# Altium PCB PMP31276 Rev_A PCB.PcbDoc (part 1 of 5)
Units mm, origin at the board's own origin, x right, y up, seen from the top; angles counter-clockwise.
Board outline 228.6 x 203.2 mm, 4 copper layers (Top Layer, Layer 1, Layer 2, Bottom Layer), stack 1.998 mm thick; 375 components, 187 nets, 994 pads, 546 vias.
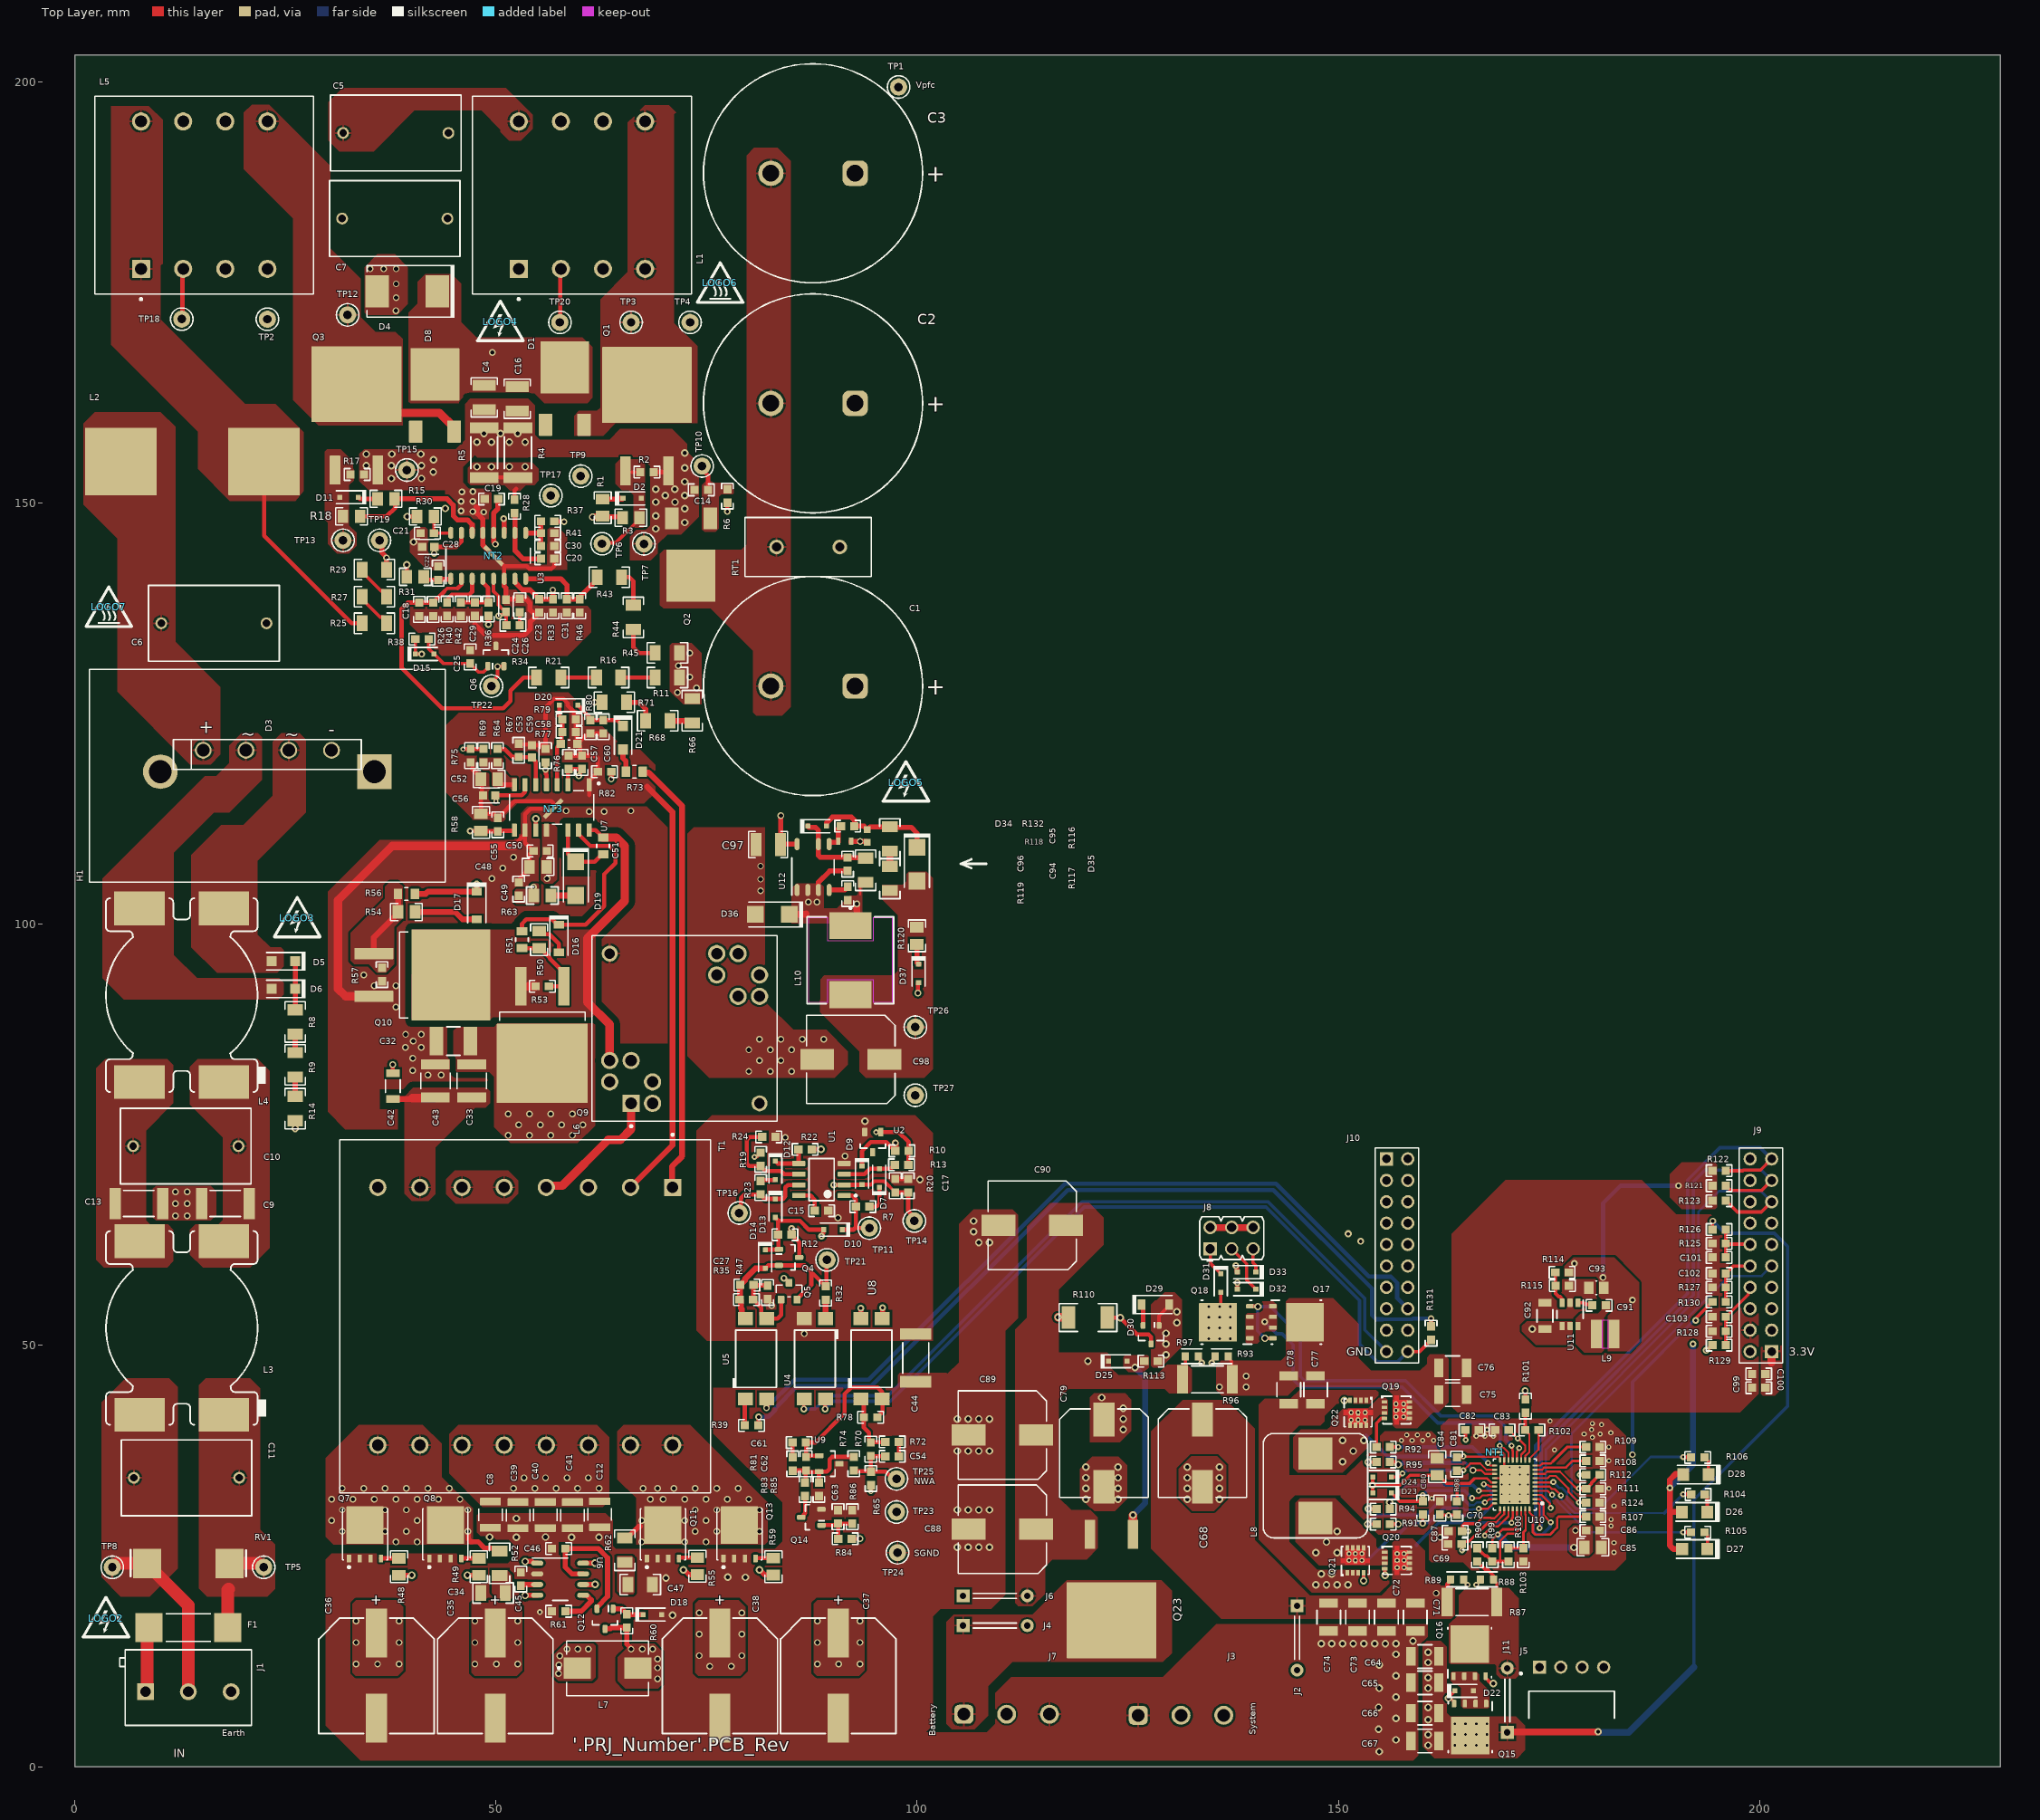
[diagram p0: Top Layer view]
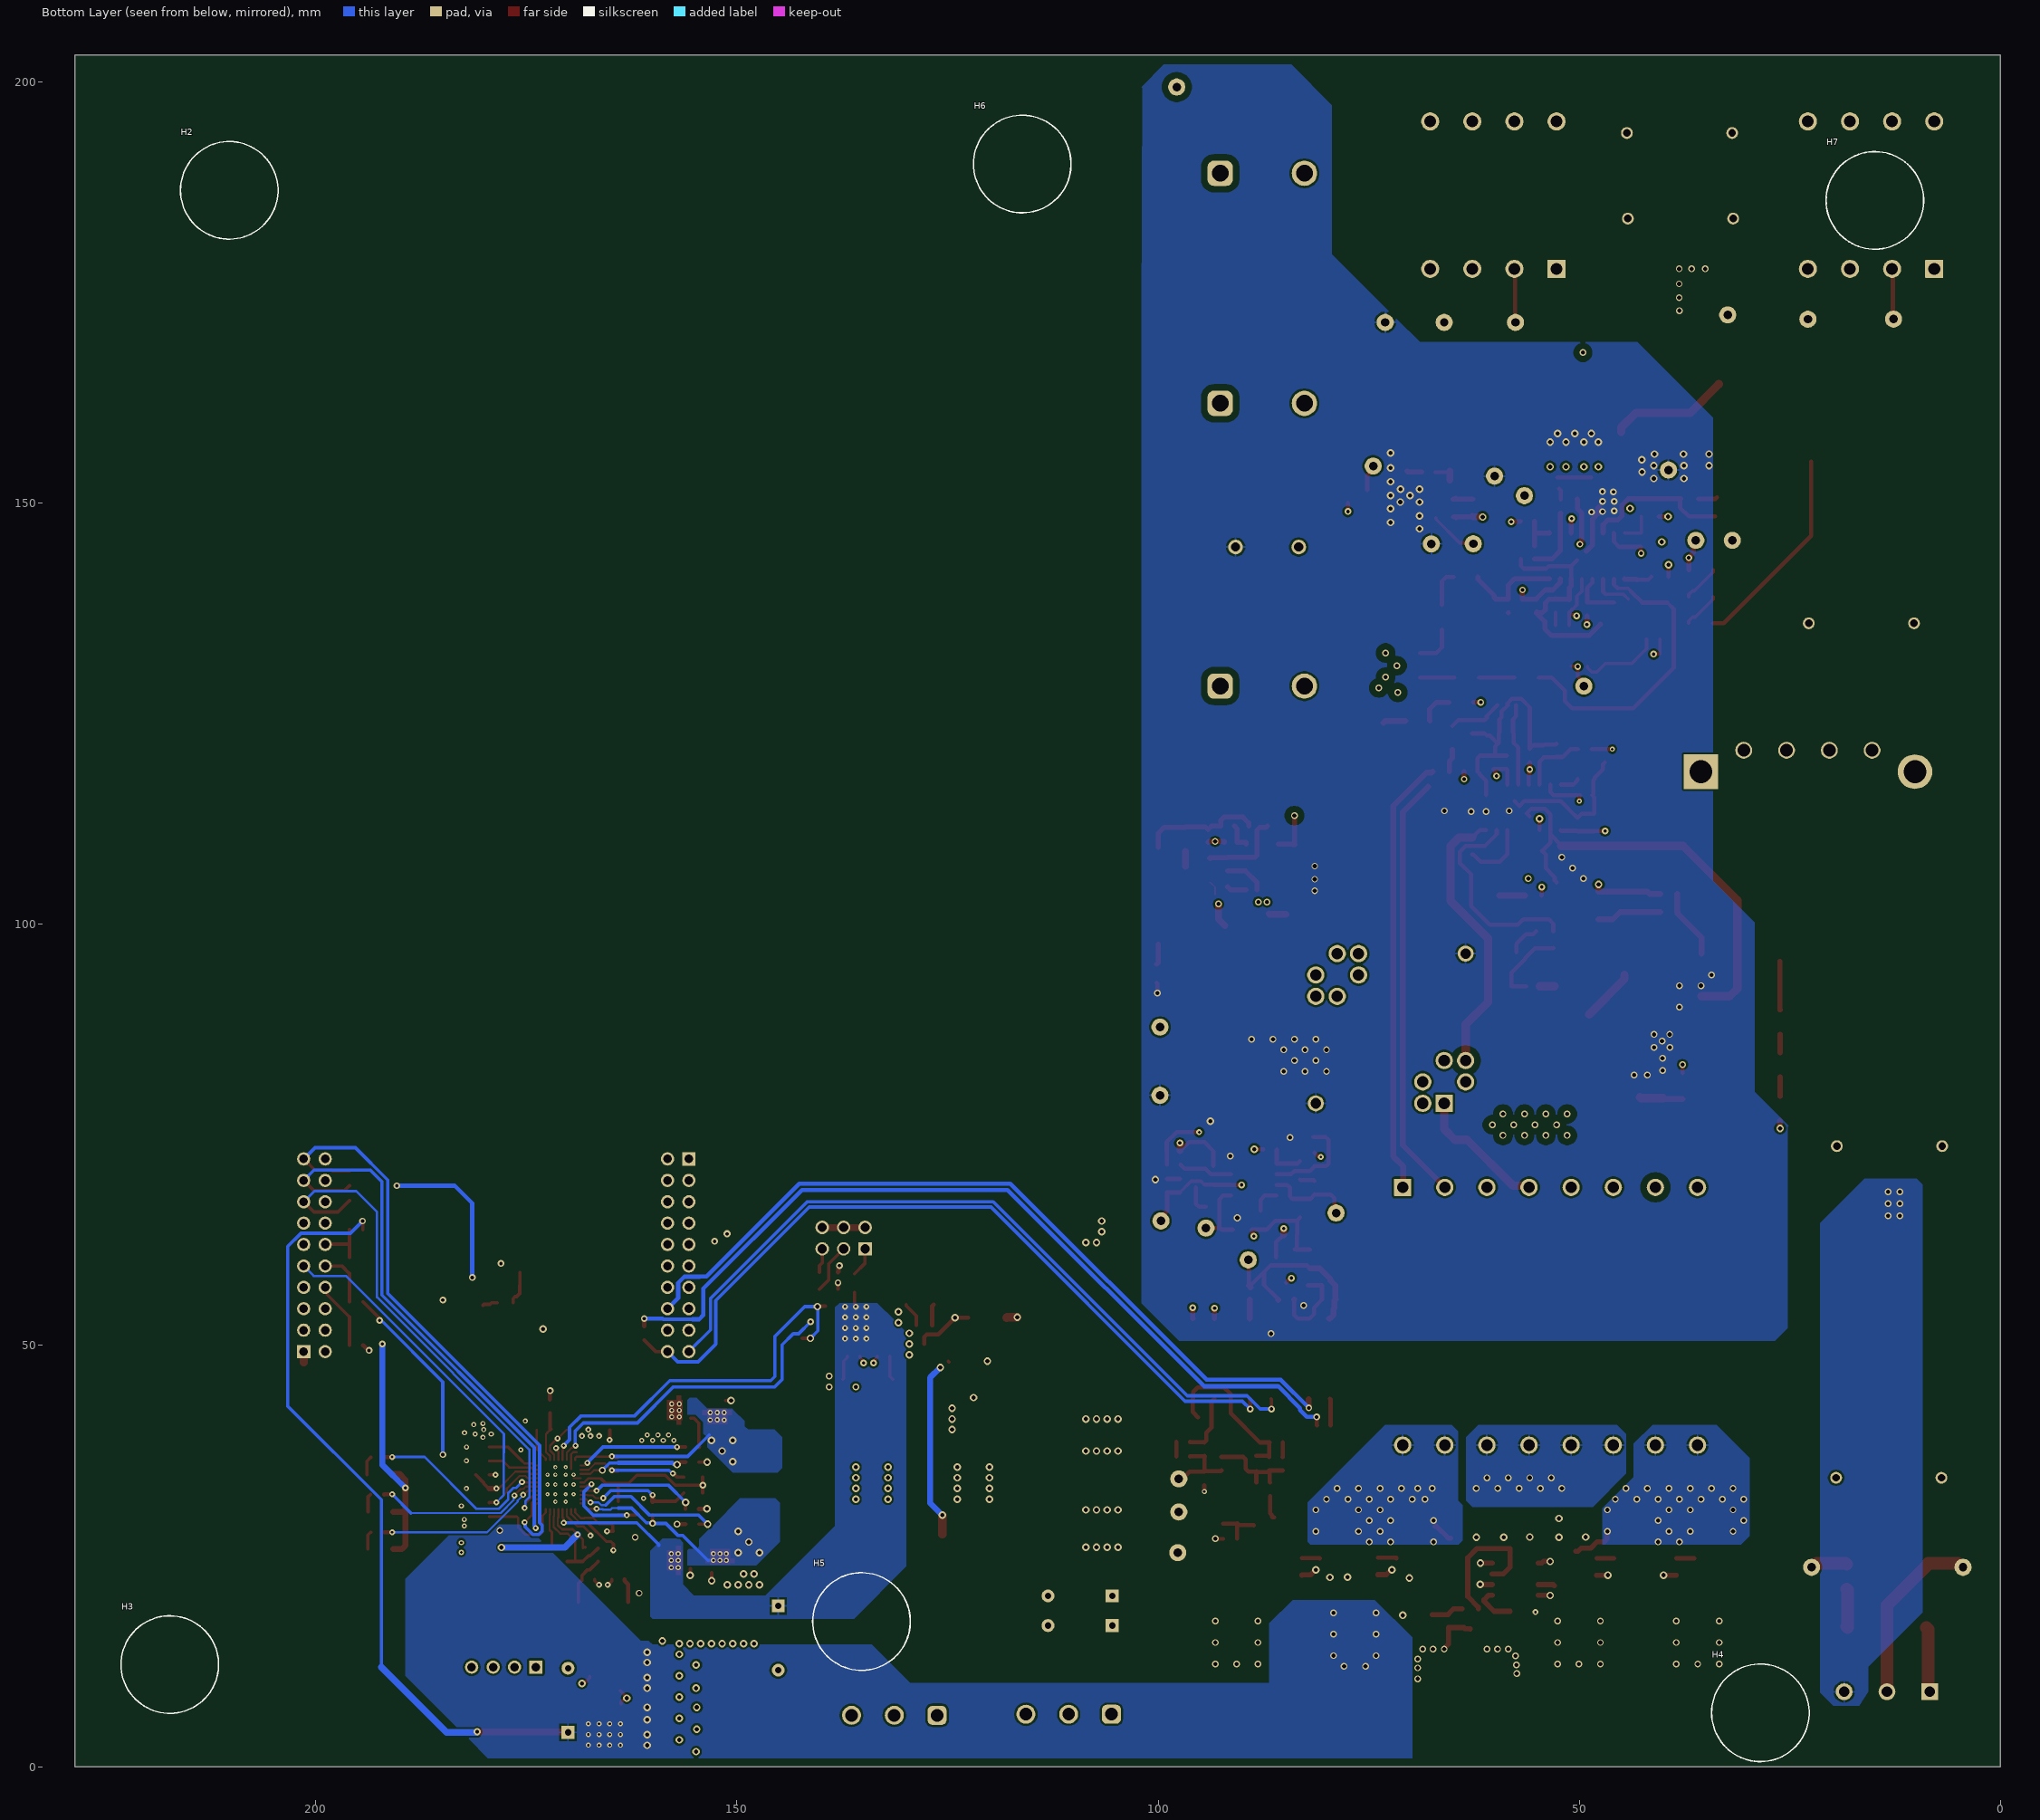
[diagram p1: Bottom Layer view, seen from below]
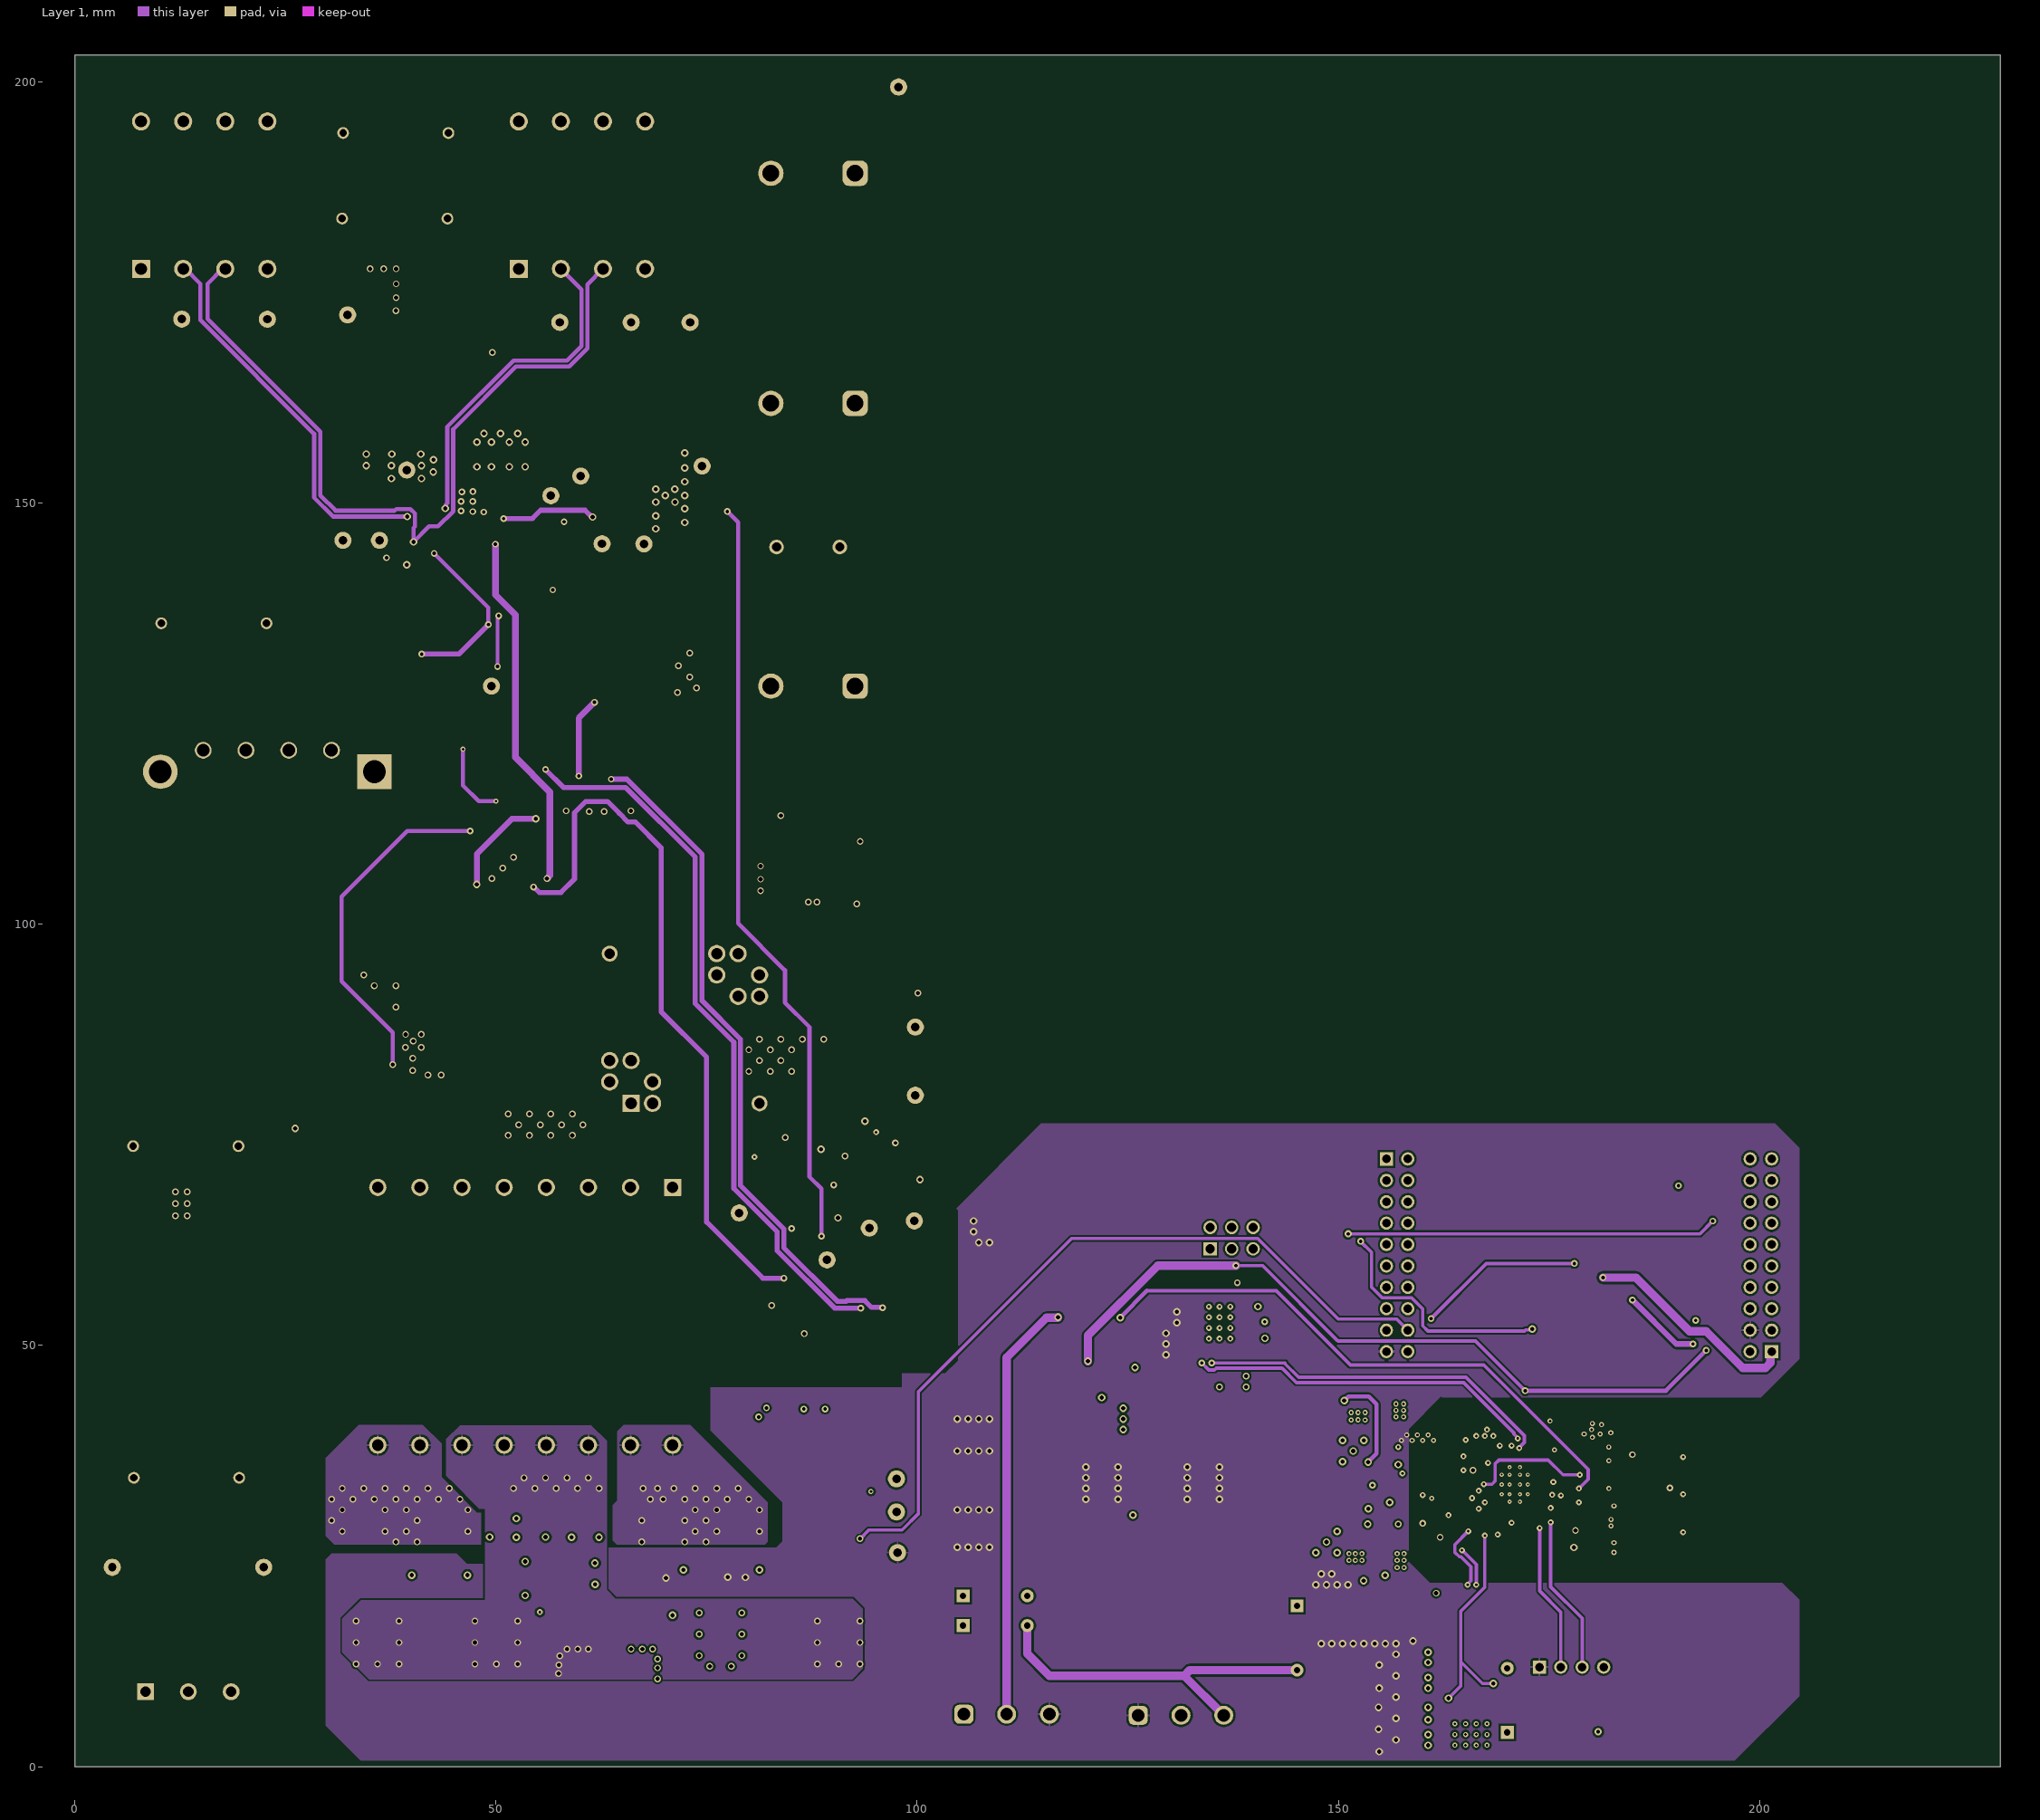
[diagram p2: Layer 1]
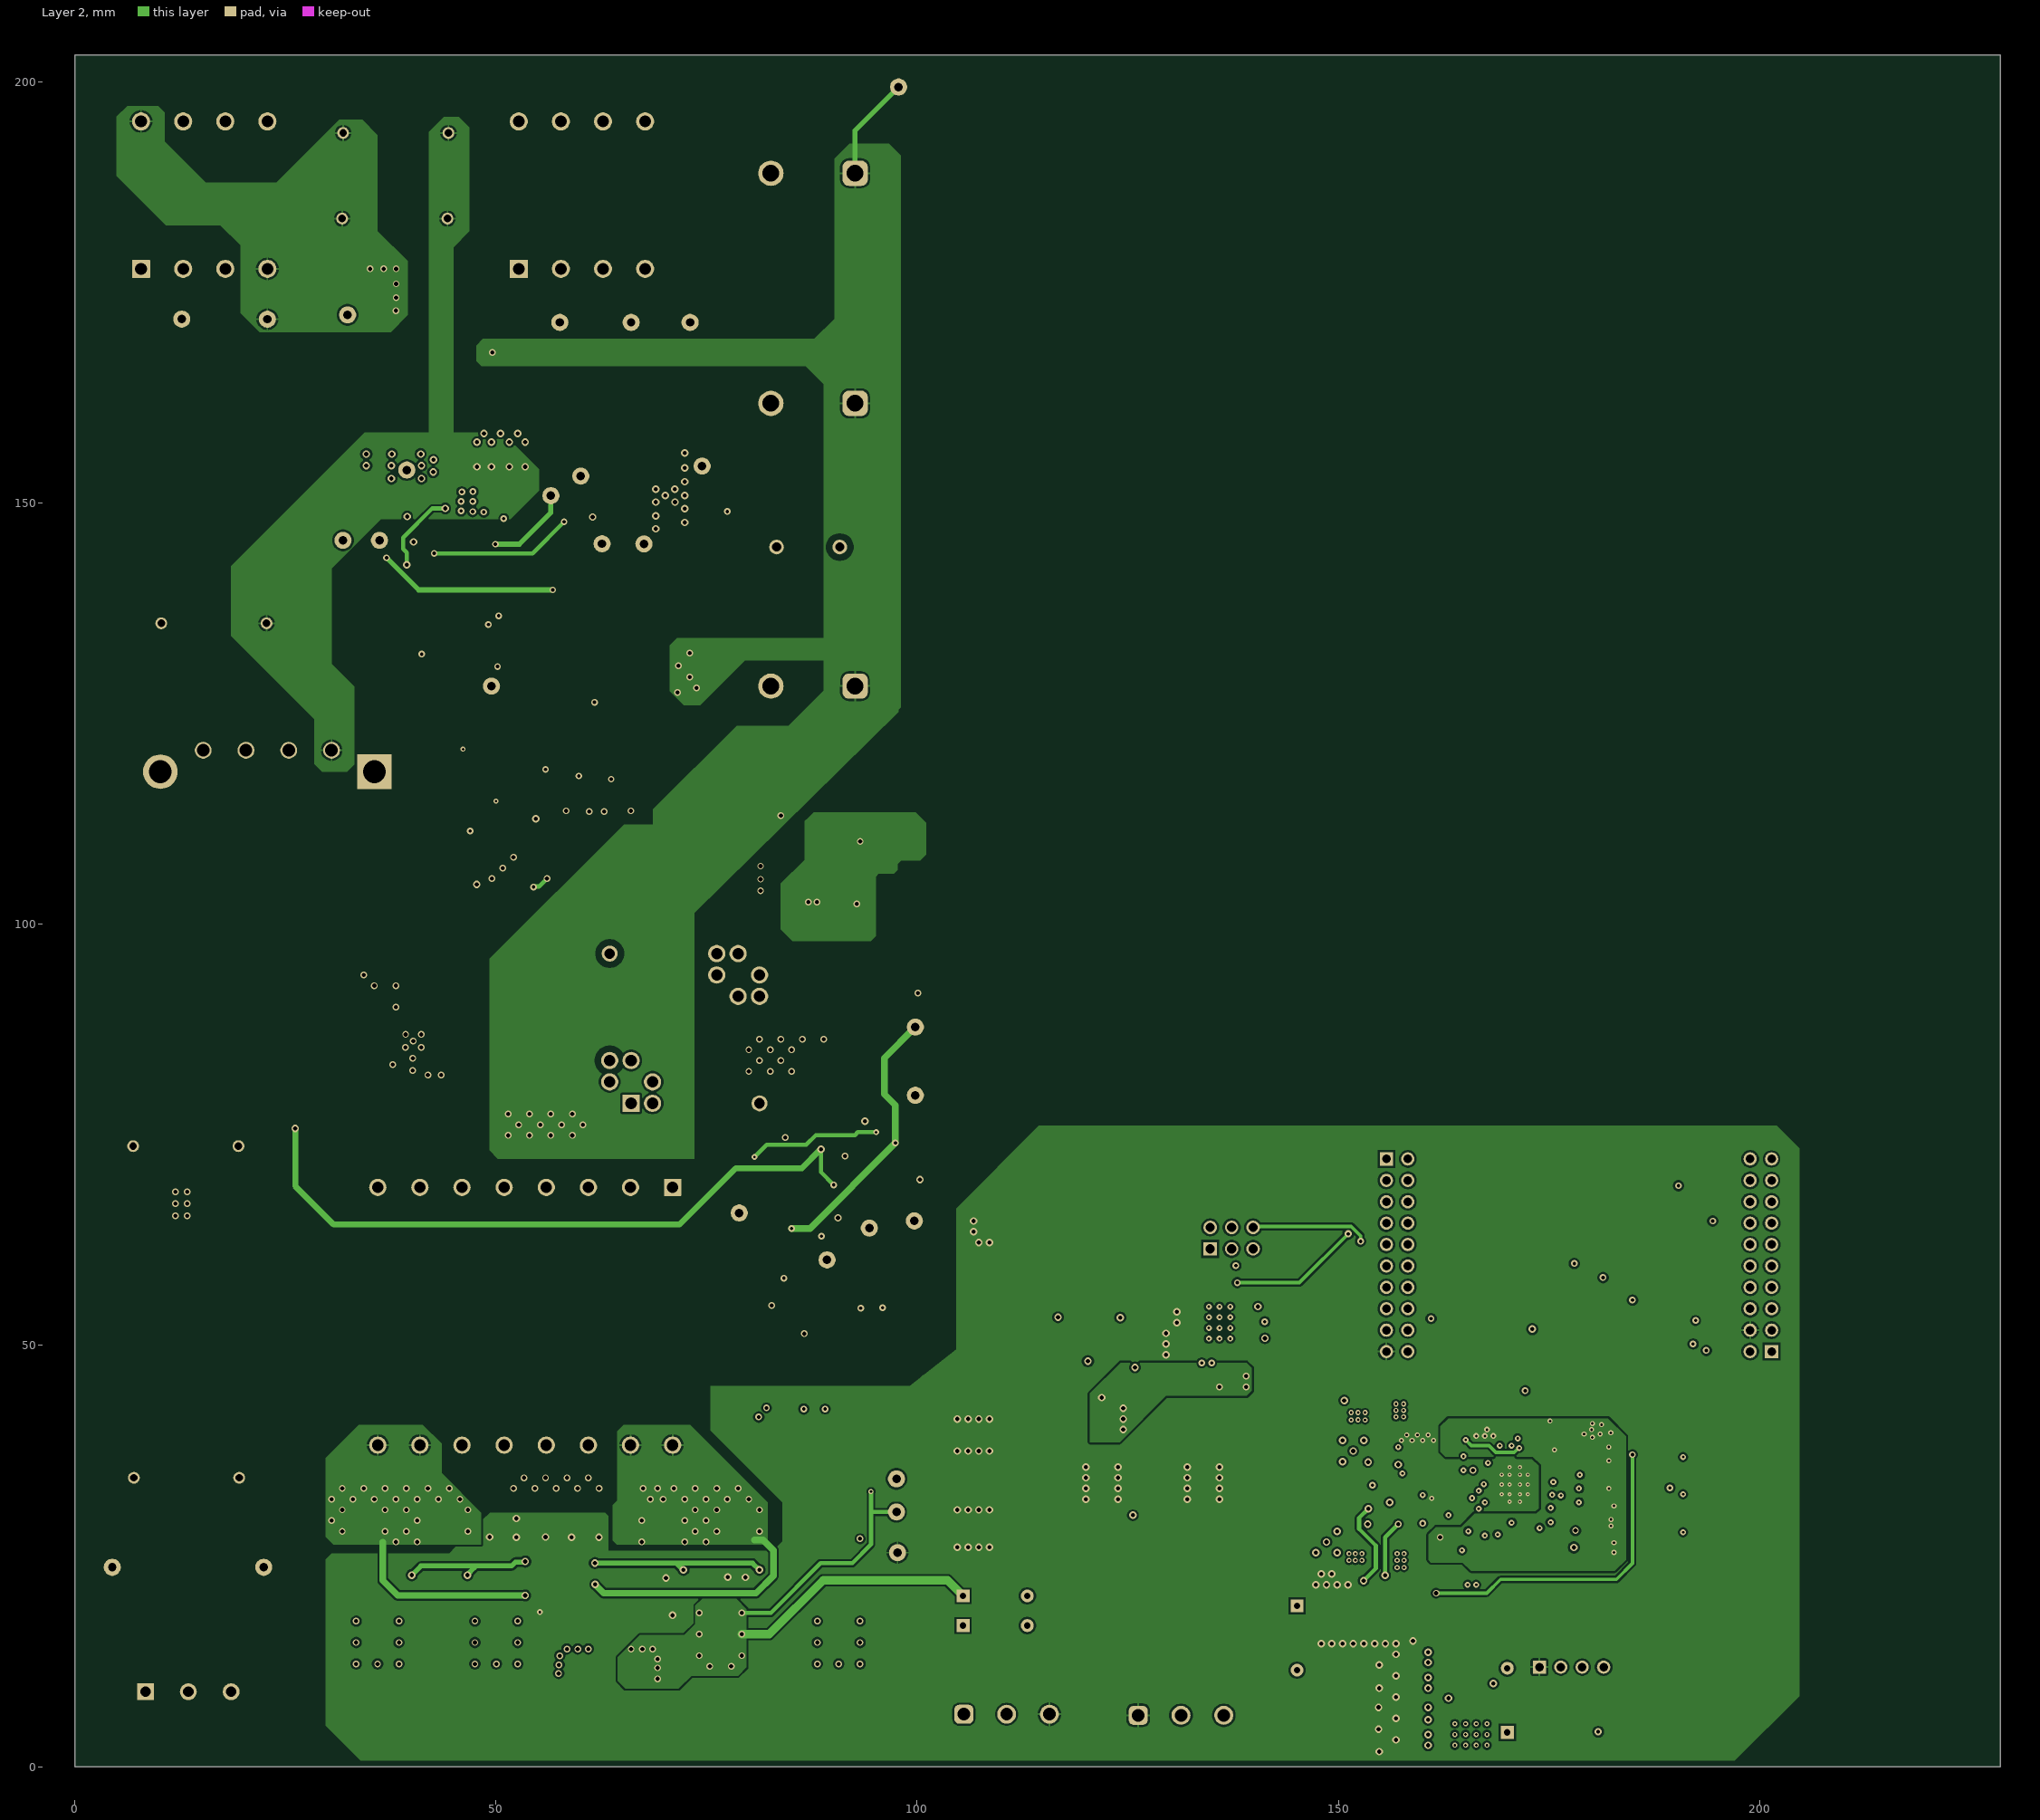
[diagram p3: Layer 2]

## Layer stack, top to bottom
Top Solder: solder mask 0.0102, Solder Resist, Dk 3.5
Top Layer: signal copper 0.07
Dielectric 1: prepreg 0.0711, PP-006, Dk 4.1
Layer 1: signal copper 0.035
Dielectric 3: prepreg 0.0711, PP-006, Dk 4.1
Dielectric1: core 1.5037, FR-4 High Tg, Dk 4.8
Dielectric 4: prepreg 0.0711, PP-006, Dk 4.1
Layer 2: signal copper 0.035
Dielectric 2: prepreg 0.0711, PP-006, Dk 4.1
Bottom Layer: signal copper 0.07
Bottom Solder: solder mask 0.0102, Solder Resist, Dk 3.5

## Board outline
0,0 228.6,0 228.6,203.2 0,203.2

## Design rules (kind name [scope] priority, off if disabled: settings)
AcuteAngle [All] p1: minimum=4.50000000000000E+0001 checktracksonly=FALSE
AssemblyTestPointUsage [All] p1: valid=2
BoardOutlineClearance BoardOutlineClearance_MountingHoles [OnCopper and InComponentClass('Mounting Holes')] p1: gap=1 ignorepadtopadclearanceinfootprint=FALSE
BoardOutlineClearance BoardOutlineClearance_Poly [OnCopper and IsPoly] p2: gap=0.635 ignorepadtopadclearanceinfootprint=FALSE
BoardOutlineClearance [OnCopper and Not InComponentClass('Logo') and not InComponentClass('FiducialMark') and not InRegion(1000,500,4000,800) and not InPoly] p3: gap=1.016 ignorepadtopadclearanceinfootprint=FALSE
Clearance "Clearance HV" [InNet('SW') vs InNet('PGND')] p1: gap=0.75 ignorepadtopadclearanceinfootprint=TRUE
Clearance "Clearance HV_1" [InNet('SW') vs InNet('Vpfc')] p2: gap=0.75 ignorepadtopadclearanceinfootprint=TRUE
Clearance "Clearance Q9-gate" [InNet('NetQ9_1') vs InNet('PGND')] p3: gap=0.75 ignorepadtopadclearanceinfootprint=TRUE
Clearance "Clearance HDRV-G" [InNet('HDRV-G') vs InNet('PGND')] p4: gap=0.75 ignorepadtopadclearanceinfootprint=TRUE
Clearance "Clearance C51-2" [InNet('NetC51_2') vs InNet('PGND')] p5: gap=0.75 ignorepadtopadclearanceinfootprint=TRUE
Clearance "Clearance Vpfc" [InNet('Vpfc') vs InNet('PGND')] p6: gap=0.75 ignorepadtopadclearanceinfootprint=TRUE
Clearance "Clearance C33-1" [InNet('NetC33_1') vs InNet('PGND')] p7: gap=0.75 ignorepadtopadclearanceinfootprint=TRUE
Clearance Clearance_U10 [InComponent('U10')] p8: gap=0.25 ignorepadtopadclearanceinfootprint=TRUE
Clearance "Schematic Clearance Constraint_54" [InNet('3V3')] p9: gap=0.254 ignorepadtopadclearanceinfootprint=FALSE
Clearance "Schematic Clearance Constraint_53" [InNet('AGND')] p10: gap=0.254 ignorepadtopadclearanceinfootprint=FALSE
Clearance "Schematic Clearance Constraint_52" [InNet('BAT_SRC')] p11: gap=0.254 ignorepadtopadclearanceinfootprint=FALSE
Clearance "Schematic Clearance Constraint_51" [InNet('BQ_CE')] p12: gap=0.254 ignorepadtopadclearanceinfootprint=FALSE
Clearance "Schematic Clearance Constraint_50" [InNet('NetD22_2')] p13: gap=0.254 ignorepadtopadclearanceinfootprint=FALSE
Clearance "Schematic Clearance Constraint_49" [InNet('BAT')] p14: gap=0.254 ignorepadtopadclearanceinfootprint=FALSE
Clearance "Schematic Clearance Constraint_48" [InNet('NetJ11_2')] p15: gap=0.254 ignorepadtopadclearanceinfootprint=FALSE
Clearance "Schematic Clearance Constraint_47" [InNet('NetR114_1')] p16: gap=0.254 ignorepadtopadclearanceinfootprint=FALSE
Clearance "Schematic Clearance Constraint_46" [InNet('NetC91_2')] p17: gap=0.254 ignorepadtopadclearanceinfootprint=FALSE
Clearance "Schematic Clearance Constraint_45" [InNet('NetC75_1')] p18: gap=0.254 ignorepadtopadclearanceinfootprint=FALSE
Clearance "Schematic Clearance Constraint_44" [InNet('NetC92_2')] p19: gap=0.254 ignorepadtopadclearanceinfootprint=FALSE
Clearance "Schematic Clearance Constraint_43" [InNet('24V/27.6V')] p20: gap=0.229 ignorepadtopadclearanceinfootprint=FALSE
Clearance "Schematic Clearance Constraint_42" [InNet('AC_DC_on')] p21: gap=0.229 ignorepadtopadclearanceinfootprint=FALSE
Clearance "Schematic Clearance Constraint_41" [InNet('NetR92_2')] p22: gap=0.229 ignorepadtopadclearanceinfootprint=FALSE
Clearance "Schematic Clearance Constraint_40" [InNet('NetR100_1')] p23: gap=0.229 ignorepadtopadclearanceinfootprint=FALSE
Clearance "Schematic Clearance Constraint_39" [InNet('NetC102_1')] p24: gap=0.229 ignorepadtopadclearanceinfootprint=FALSE
Clearance "Schematic Clearance Constraint_38" [InNet('NetC70_2')] p25: gap=0.229 ignorepadtopadclearanceinfootprint=FALSE
Clearance "Schematic Clearance Constraint_37" [InNet('NetR102_2')] p26: gap=0.229 ignorepadtopadclearanceinfootprint=FALSE
Clearance "Schematic Clearance Constraint_36" [InNet('NetR105_2')] p27: gap=0.229 ignorepadtopadclearanceinfootprint=FALSE
Clearance "Schematic Clearance Constraint_35" [InNet('NetR94_2')] p28: gap=0.229 ignorepadtopadclearanceinfootprint=FALSE
Clearance "Schematic Clearance Constraint_34" [InNet('BQ_INT')] p29: gap=0.229 ignorepadtopadclearanceinfootprint=FALSE
Clearance "Schematic Clearance Constraint_33" [InNet('DRV_SUP')] p30: gap=0.229 ignorepadtopadclearanceinfootprint=FALSE
Clearance "Schematic Clearance Constraint_32" [InNet('NetQ22_4')] p31: gap=0.229 ignorepadtopadclearanceinfootprint=FALSE
Clearance "Schematic Clearance Constraint_31" [InNet('NetD29_1')] p32: gap=0.229 ignorepadtopadclearanceinfootprint=FALSE
Clearance "Schematic Clearance Constraint_30" [InNet('NetR101_2')] p33: gap=0.229 ignorepadtopadclearanceinfootprint=FALSE
Clearance "Schematic Clearance Constraint_29" [InNet('BAT_DRV')] p34: gap=0.229 ignorepadtopadclearanceinfootprint=FALSE
Clearance "Schematic Clearance Constraint_28" [InNet('NetJ7_2')] p35: gap=0.229 ignorepadtopadclearanceinfootprint=FALSE
Clearance "Schematic Clearance Constraint_27" [InNet('NetC101_1')] p36: gap=0.229 ignorepadtopadclearanceinfootprint=FALSE
Clearance "Schematic Clearance Constraint_26" [InNet('SDA')] p37: gap=0.229 ignorepadtopadclearanceinfootprint=FALSE
Clearance "Schematic Clearance Constraint_25" [InNet('NetC81_1')] p38: gap=0.229 ignorepadtopadclearanceinfootprint=FALSE
Clearance "Schematic Clearance Constraint_24" [InNet('NetC83_1')] p39: gap=0.229 ignorepadtopadclearanceinfootprint=FALSE
Clearance "Schematic Clearance Constraint_23" [InNet('NetR95_2')] p40: gap=0.229 ignorepadtopadclearanceinfootprint=FALSE
Clearance "Schematic Clearance Constraint_22" [InNet('NetQ20_4')] p41: gap=0.229 ignorepadtopadclearanceinfootprint=FALSE
Clearance "Schematic Clearance Constraint_21" [InNet('SYSTEM')] p42: gap=0.229 ignorepadtopadclearanceinfootprint=FALSE
Clearance "Schematic Clearance Constraint_20" [InNet('NetJ4_1')] p43: gap=0.229 ignorepadtopadclearanceinfootprint=FALSE
Clearance "Schematic Clearance Constraint_19" [InNet('NetD22_1')] p44: gap=0.229 ignorepadtopadclearanceinfootprint=FALSE
Clearance "Schematic Clearance Constraint_18" [InNet('NetD25_2')] p45: gap=0.229 ignorepadtopadclearanceinfootprint=FALSE
Clearance "Schematic Clearance Constraint_17" [InNet('NetQ21_4')] p46: gap=0.229 ignorepadtopadclearanceinfootprint=FALSE
Clearance "Schematic Clearance Constraint_16" [InNet('NetR107_2')] p47: gap=0.229 ignorepadtopadclearanceinfootprint=FALSE
Clearance "Schematic Clearance Constraint_15" [InNet('NetC80_2')] p48: gap=0.229 ignorepadtopadclearanceinfootprint=FALSE
Clearance "Schematic Clearance Constraint_14" [InNet('NetR109_2')] p49: gap=0.229 ignorepadtopadclearanceinfootprint=FALSE
Clearance "Schematic Clearance Constraint_13" [InNet('NetR91_1')] p50: gap=0.229 ignorepadtopadclearanceinfootprint=FALSE
Clearance "Schematic Clearance Constraint_12" [InNet('NetC82_2')] p51: gap=0.229 ignorepadtopadclearanceinfootprint=FALSE
Clearance "Schematic Clearance Constraint_11" [InNet('NetC80_1')] p52: gap=0.229 ignorepadtopadclearanceinfootprint=FALSE
Clearance "Schematic Clearance Constraint_10" [InNet('NetR104_2')] p53: gap=0.229 ignorepadtopadclearanceinfootprint=FALSE
Clearance "Schematic Clearance Constraint_9" [InNet('NetR90_1')] p54: gap=0.229 ignorepadtopadclearanceinfootprint=FALSE
Clearance "Schematic Clearance Constraint_8" [InNet('NetC81_2')] p55: gap=0.229 ignorepadtopadclearanceinfootprint=FALSE
Clearance "Schematic Clearance Constraint_7" [InNet('NetQ19_4')] p56: gap=0.229 ignorepadtopadclearanceinfootprint=FALSE
Clearance "Schematic Clearance Constraint_6" [InNet('NetC103_1')] p57: gap=0.229 ignorepadtopadclearanceinfootprint=FALSE
Clearance "Schematic Clearance Constraint_5" [InNet('NetR108_2')] p58: gap=0.229 ignorepadtopadclearanceinfootprint=FALSE
Clearance "Schematic Clearance Constraint_4" [InNet('REG_N')] p59: gap=0.229 ignorepadtopadclearanceinfootprint=FALSE
Clearance "Schematic Clearance Constraint_3" [InNet('VAC_OK_SEC')] p60: gap=0.229 ignorepadtopadclearanceinfootprint=FALSE
Clearance "Schematic Clearance Constraint_2" [InNet('SCL')] p61: gap=0.229 ignorepadtopadclearanceinfootprint=FALSE
Clearance "Schematic Clearance Constraint_1" [InNet('NetC69_1')] p62: gap=0.229 ignorepadtopadclearanceinfootprint=FALSE
Clearance "Schematic Clearance Constraint" [InNet('NetR106_2')] p63: gap=0.229 ignorepadtopadclearanceinfootprint=FALSE
Clearance Clearance_Keepouts [((IsTrack Or IsArc) And Not InPoly) And IsFree and IsKeepOut vs ((IsTrack Or IsArc) And Not InPoly) And IsFree and IsKeepOut] p64: gap=0 ignorepadtopadclearanceinfootprint=FALSE
Clearance Clearance_Poly [InPolygon] p65: gap=0.254 ignorepadtopadclearanceinfootprint=TRUE except(0.2: Arc-Arc Arc-Track Arc-SMDPad Track-Track Track-SMDPad)
Clearance Clearance_FiducialMark [IsKeepOut and InComponentClass('FiducialMark') vs IsPad and InComponentClass('FiducialMark')] p66: gap=0 ignorepadtopadclearanceinfootprint=FALSE
Clearance "Clearance between HV Net and others" [InNetClass('HV') vs InNet('PGND')] p67: gap=1 ignorepadtopadclearanceinfootprint=TRUE
ComponentClearance ComponentClearance_1 [InComponent('NT2') vs InComponent('U3')] p1: gap=0 collisioncheckmode=3 verticalgap=0 showdistances=FALSE
ComponentClearance ComponentClearance_2 [InComponent('NT3') vs InComponent('U7')] p2: gap=0 collisioncheckmode=3 verticalgap=0 showdistances=FALSE
ComponentClearance ComponentClearance_MountingHoles_FiducialMarks [InComponentClass('Mounting Holes') vs InComponentClass('FiducialMark')] p3: gap=1.27 collisioncheckmode=3 verticalgap=0.254 showdistances=FALSE
ComponentClearance ComponentClearance_Shunt [InComponentClass('Header') vs InComponentClass('Shunt')] p4: gap=0 collisioncheckmode=3 verticalgap=0 showdistances=FALSE
ComponentClearance ComponentClearance_Logo [InComponentClass('Logo')] p5: gap=0.762 collisioncheckmode=3 verticalgap=0.254 showdistances=FALSE
ComponentClearance ComponentClearance_ScrewToNut [(HasFootprint('NY PMS 440 0025 PH')) vs (HasFootprint('Keystone_1902C'))] p6: gap=0.127 collisioncheckmode=3 verticalgap=0.254 showdistances=FALSE
ComponentClearance ComponentClearance_MountingHoles [InComponentClass('Mounting Holes')] p7: gap=2.54 collisioncheckmode=3 verticalgap=2540 showdistances=FALSE
ComponentClearance ComponentClearance_SmallPassives [HasFootprint('0201*') or HasFootprint('0402*') or HasFootprint('0508') or HasFootprint('0603*') or HasFootprint('0612') or HasFootprint('0805*') or HasFootprint('0815*') or HasFootprint('0830*') or HasFootprint('1206*') or HasFootprint('1210*') or HasFootprint('1808*') or HasFootprint('1812*') or HasFootprint('1825*') or HasFootprint('2010*') or HasFootprint('2220*') or HasFootprint('2225*') or HasFootprint('2512*') or HasFootprint('2728*') or HasFootprint('3518*') vs HasFootprint('0201*') or HasFootprint('0402*') or HasFootprint('0508') or HasFootprint('0603*') or HasFootprint('0612') or HasFootprint('0805*') or HasFootprint('0815*') or HasFootprint('0830*') or HasFootprint('1206*') or HasFootprint('1210*') or HasFootprint('1808*') or HasFootprint('1812*') or HasFootprint('1825*') or HasFootprint('2010*') or HasFootprint('2220*') or HasFootprint('2225*') or HasFootprint('2512*') or HasFootprint('2728*') or HasFootprint('3518*')] p8: gap=0.254 collisioncheckmode=3 verticalgap=0.254 showdistances=FALSE
ComponentClearance ComponentClearance_THtoSMT [IsThruComponent vs IsSMTComponent] p9: gap=0.762 collisioncheckmode=3 verticalgap=0.762 showdistances=FALSE
ComponentClearance ComponentClearance_THtoTH [IsThruComponent vs IsThruComponent] p10: gap=0.508 collisioncheckmode=3 verticalgap=0.762 showdistances=FALSE
ComponentClearance [All] p11: gap=0.508 collisioncheckmode=3 verticalgap=0.254 showdistances=FALSE
DiffPairsRouting [All] p1: maxlimit=2.54 minlimit=0.254 mostfreqgap=0.254 toplayer_minwidth=0.381 toplayer_maxwidth=0.381 toplayer_prefwidth=0.381 midlayer1_minwidth=0.381 midlayer1_maxwidth=0.381 midlayer1_prefwidth=0.381 midlayer2_minwidth=0.381 midlayer2_maxwidth=0.381 midlayer2_prefwidth=0.381 bottomlayer_minwidth=0.381 bottomlayer_maxwidth=0.381 bottomlayer_prefwidth=0.381 maxuncoupledlength=25.4
FabricationTestPointUsage TestPointUsage [All] p1: valid=2 allowmultiple=FALSE
FabricationTestpoint Testpoint [All] p1: side=3 testpointundercomponent=TRUE minsize=1.016 maxsize=2.54 preferedsize=1.524 minholesize=0 maxholesize=1.016 preferedholesize=0.813 testpointgrid=0.025 allowsidetop=TRUE allowsidebottom=TRUE usegrid=TRUE gridtolerance=0
FanoutControl Fanout_LCC [IsLCC] p1: bgadir=Out bgaviamode=Centered fanoutstyle=Auto fanoutdirection=Alternating viagrid=0.025 // Fanout_LCC (Default Rule)
FanoutControl Fanout_BGA [IsBGA] p2: bgadir=Out bgaviamode=Centered fanoutstyle=Auto fanoutdirection=Alternating viagrid=0.025 // Fanout_BGA (Default Rule)
FanoutControl Fanout_Default [All] p4: bgadir=Out bgaviamode=Centered fanoutstyle=Auto fanoutdirection=Alternating viagrid=0.025 // Fanout_Default (Default Rule)
FanoutControl Fanout_Small [(CompPinCount < 5)] p5: bgadir=Out bgaviamode=Centered fanoutstyle=Auto fanoutdirection=OutThenIn viagrid=0.025 // Fanout_Small (Default Rule)
HoleSize [All] p1: absolutevalues=TRUE maxlimit=6.375 minlimit=0.2 maxpercent=80.000 minpercent=20.000
MinimumAnnularRing MinimumAnnularRing_ThermalPadVias [IsVia and InAnyComponent] p1: minimumring=0.15
MinimumAnnularRing [All] p2: minimumring=0.15
MinimumSolderMaskSliver MinimumSolderMaskSliver_Logo [InComponentClass('Logo') vs InComponentClass('Logo')] p1: minsoldermaskwidth=0.018
MinimumSolderMaskSliver [All] p2: minsoldermaskwidth=0.1
PlaneConnect [All] p1: planeconnectstyle=Relief reliefexpansion=0.254 reliefentries=4 reliefconductorwidth=0.254 reliefairgap=0.254
PolygonConnect PolygonConnect_1 [HasPad('U4-3')] p1: thpad.connectstyle=Relief thpad.reliefconductorwidth=0.254 thpad.reliefentries=4 thpad.polygonreliefangle="90 Angle" thpad.airgapwidth=0.254 smdpad.connectstyle=NoConnect smdpad.reliefconductorwidth=0.254 smdpad.reliefentries=4 smdpad.polygonreliefangle="90 Angle" smdpad.airgapwidth=0.254 via.connectstyle=Direct via.reliefconductorwidth=0.254 via.reliefentries=4 via.polygonreliefangle="90 Angle" via.airgapwidth=0.254
PolygonConnect [All] p2: thpad.connectstyle=Relief thpad.reliefconductorwidth=0.254 thpad.reliefentries=4 thpad.polygonreliefangle="90 Angle" thpad.airgapwidth=0.254 smdpad.connectstyle=Direct smdpad.reliefconductorwidth=0.254 smdpad.reliefentries=4 smdpad.polygonreliefangle="90 Angle" smdpad.airgapwidth=0.254 via.connectstyle=Direct via.reliefconductorwidth=0.254 via.reliefentries=4 via.polygonreliefangle="90 Angle" via.airgapwidth=0.254
RoutingVias ThermalPadVias [IsVia and InAnyComponent] p1: holewidth=0.2 width=0.5 viastyle="Through Hole" minholewidth=0.2 minwidth=0.5 maxholewidth=0.33 maxwidth=0.6
RoutingVias [All] p2: holewidth=0.406 width=0.864 viastyle="Through Hole" minholewidth=0.2 minwidth=0.5 maxholewidth=1.016 maxwidth=1.651
SilkToBoardRegionClearance [Not ((IsComment or IsDesignator) And (Hide <> 'False')) and not InRegion(1000,500,4000,800)] p1:
SilkToSilkClearance SilkToSilkClearance_Pb-FreeLogo [(HasFootprint('Pb-Free_Overlay_Medium') OR HasFootprint('Pb-Free_Overlay_Small')) vs (HasFootprint('Pb-Free_Overlay_Medium') OR HasFootprint('Pb-Free_Overlay_Small'))] p1: silktosilkclearance=0
SilkToSilkClearance [All] p2: silktosilkclearance=0.1
SilkToSolderMaskClearance SilkToComponentPadClearance [(IsPad or IsFill or IsRegion) and InAnycomponent] p1: minsilkscreentomaskgap=0.127 clearancetoexposedcopper=TRUE
SilkToSolderMaskClearance "Silk to Solder Mask Opening" [All] p2: minsilkscreentomaskgap=0.1 clearancetoexposedcopper=FALSE
SolderMaskExpansion [All] p1: expansion=0.05 istentingtop=FALSE
UnRoutedNet [All] p1: checkbadconnections=TRUE
Width [All] p1: maxlimit=2.54 minlimit=0.152 preferedwidth=0.254 checkconnectedcopper=TRUE
14 further rules are at their usual default settings.

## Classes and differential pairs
net class HV: net_D1_3 NetC6_2 NetD5_1 NetD8_3 VAC Vpfc
component class "PMP31276 Rev_A PFC Schematic": C1 C2 C3 C4 C5 C6 C7 C9 C10 C11 C13 C14 C15 C16 C17 C18 C19 C20 C21 C22 C23 C24 C25 C26 C27 C28 C29 C30 C31 D1 D2 D3 D4 D5 D6 D7 D8 D9 D10 D11 D12 D13 D14 D15 F1 H1 J1 L1 L2 L3 L4 L5 NT2 Q1 Q2 Q3 Q4 Q5 Q6 R1 R2 R3 R4 R5 R6 R7 R8 R9 R10 R11 R12 R13 R14 R15 R16 R17 R18 R19 R20 R21 R22 R23 R24 R25 R26 R27 R28 R29 R30 R31 R32 R33 R34 R35 R36 R37 R38 R39 R40 R41 R42 R43 R44 R45 R46 R47 RT1 RV1 TP1 TP2 TP3 TP4 TP5 TP6 TP7 TP8 TP9 TP10 TP11 TP12 TP13 TP14 TP15 TP16 TP17 TP18 TP19 TP20 TP21 TP22 U1 U2 U3 U4 U5
component class "PMP31276 Rev_A LLC Schematic": C8 C12 C32 C33 C34 C35 C36 C37 C38 C39 C40 C41 C42 C43 C44 C45 C46 C47 C48 C49 C50 C51 C52 C53 C54 C55 C56 C57 C58 C59 C60 C61 C62 C63 D16 D17 D18 D19 D20 D21 L6 L7 NT3 Q7 Q8 Q9 Q10 Q11 Q12 Q13 Q14 R48 R49 R50 R51 R52 R53 R54 R55 R56 R57 R58 R59 R60 R61 R62 R63 R64 R65 R66 R67 R68 R69 R70 R71 R72 R73 R74 R75 R76 R77 R78 R79 R80 R81 R82 R83 R84 R85 R86 T1 TP23 TP24 TP25 U6 U7 U8 U9
component class "PMP31276 Rev_A LaunchPad and Aux-PSU Schematic": C91 C92 C93 C94 C95 C96 C97 C98 C99 C100 C101 C102 C103 D31 D32 D33 D34 D35 D36 D37 J8 J9 J10 L9 L10 R114 R115 R116 R117 R118 R119 R120 R121 R122 R123 R124 R125 R126 R127 R128 R129 R130 R131 R132 TP26 TP27 U11 U12
component class "PMP31276 Rev_A Hardware": H2 H3 H4 H5 H6 H7 H8 H9 H10 LOGO2 LOGO3 LOGO4 LOGO5 LOGO6 LOGO7
component class "PMP31276 Rev_A Charger Schematic": C64 C65 C66 C67 C68 C69 C70 C71 C72 C73 C74 C75 C76 C77 C78 C79 C80 C81 C82 C83 C84 C85 C86 C87 C88 C89 C90 D22 D23 D24 D25 D26 D27 D28 D29 D30 J2 J3 J4 J5 J6 J7 J11 L8 NT1 Q15 Q16 Q17 Q18 Q19 Q20 Q21 Q22 Q23 R87 R88 R89 R90 R91 R92 R93 R94 R95 R96 R97 R98 R99 R100 R101 R102 R103 R104 R105 R106 R107 R108 R109 R110 R111 R112 R113 U10
component class Header: J8

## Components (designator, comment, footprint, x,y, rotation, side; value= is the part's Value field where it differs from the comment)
C1 "861141484010" WCAP-AI3H_D25H30 87.63,128.27 r0 top value=120uF
C2 "861141484010" WCAP-AI3H_D25H30 87.63,161.838 r0 top value=120uF
C3 "861141484010" WCAP-AI3H_D25H30 87.63,189.15 r0 top value=120uF
C4 "885342208009" 1210 48.599,162.54 r270 top value=0.01uF
C5 "890334024003" WCAP-FTXX_L15W8.5H14 38.1,193.929 r180 top value=0.33uF
C6 "890334024003" WCAP-FTXX_L15W8.5H14 16.51,135.73 r180 top value=0.33uF
C7 "890334024003" WCAP-FTXX_L15W8.5H14 37.988,183.769 r180 top value=0.33uF
C8 "885012209073" FP-885012209073_1210-MFG 49.336,29.905 r90 top value=10µF
C9 "8853522130151" WCAP-CSSA_2211_L5.7W2.8H2.5 17.871,66.847 r180 top value=2.2nF
C10 "890334024003" WCAP-FTXX_L15W8.5H14 13.174,73.66 r0 top value=0.33uF
C11 "890334024003" WCAP-FTXX_L15W8.5H14 13.266,34.29 r0 top value=0.33uF
C12 "885012209073" FP-885012209073_1210-MFG 62.316,29.955 r90 top value=10µF
C13 "8853522130151" WCAP-CSSA_2211_L5.7W2.8H2.5 7.598,66.847 r180 top value=2.2nF
C14 "GRM188R71E474KA12D" 0603 74.37,151.566 r180 top value=0.47uF
C15 "885012206095" 0603 88.646,66.002 r0 top value=0.1uF
C16 "885342208009" 1210 52.523,162.38 r270 top value=0.01uF
C17 "GRM188R6YA225KA12D" 0603 98.933,68.961 r90 top value=2.2uF
C18 "885012206083" 0603 40.894,137.381 r270 top value=1000pF
C19 "C1608X6S1H105K080AC" 0603 49.463,150.481 r180 top value=1uF
C20 "885012206083" 0603 56.134,143.383 r0 top value=1000pF
C21 "885012006054" 0603 41.846,146.431 r180 top value=33pF
C22 "885012006054" 0603 43.136,141.68 r90 top value=33pF
C23 "885012206083" 0603 55.118,137.795 r270 top value=1000pF
C24 "C0603C221J5GAC7867" FP-C0603C221J5GAC7867_0603-IPC_B 51.181,137.795 r270 top value=220pF
C25 "C1608X6S1H105K080AC" 0603 46.924,131.743 r90 top value=1uF
C26 "C1608X6S1H105K080AC" 0603 52.832,137.833 r90 top value=1uF
C27 "885012206095" 0603 79.785,57.173 r180 top value=0.1uF
C28 "885012206125" FP-885012206125_0603-IPC_B 41.968,144.79 r0 top value=220nF
C29 "885012206087" 0603 47.498,137.414 r270 top value=4700pF
C30 "885012206087" 0603 56.134,144.907 r0 top value=4700pF
C31 "885012206083" 0603 58.42,137.795 r270 top value=1000pF
C32 "885382211002" 1812_254 44.944,86.125 r180 top value=0.1uF
C33 "CKC18C103JDGACAUTO" FP-CKC18C103KWGACAUTO_1812-MFG 47.117,81.407 r90 top value=10nF
C34 "885012008070" 1206 49.665,20.613 r0 top value=330pF
C35 "865060562010" WCAP-ASLL_D12.5H14 49.911,10.795 r90 top value=680uF
C36 "865060562010" WCAP-ASLL_D12.5H14 35.814,10.795 r90 top value=680uF
C37 "865060562010" WCAP-ASLL_D12.5H14 90.638,10.795 r90 top value=680uF
C38 "865060562010" WCAP-ASLL_D12.5H14 76.581,10.795 r90 top value=680uF
C39 "885012209073" FP-885012209073_1210-MFG 52.608,29.854 r90 top value=10µF
C40 "885012209073" FP-885012209073_1210-MFG 55.851,29.873 r90 top value=10µF
C41 "885012209073" FP-885012209073_1210-MFG 59.079,29.854 r90 top value=10µF
C42 "885342208016" WCAP-CSMH_1206_L3.2W1.6H1.25 37.75,80.786 r270 top value=150pF
C43 "CKC18C103JDGACAUTO" FP-CKC18C103KWGACAUTO_1812-MFG 42.799,81.407 r270 top value=10nF
C44 "8853522130151" WCAP-CSSA_2211_L5.7W2.8H2.5 99.822,48.514 r270 top value=2.2nF
C45 "GRM188R6YA225KA12D" 0603 52.959,22.274 r270 top value=2.2uF
C46 "GRM188R6YA225KA12D" 0603 57.435,25.884 r180 top value=2.2uF
C47 "885012008070" 1206 67.13,21.625 r180 top value=330pF
C48 "C2012X7R1V475K125AC" 0805_HV 54.991,106.807 r180 top value=4.7uF
C49 "C1608X6S1H105K080AC" 0603 52.705,104.177 r90 top value=1uF
C50 "885012206095" 0603 55.245,108.712 r180 top value=0.1uF
C51 "Capacitor" 0805_HV1 62.715,109.292 r270 top value=1uF
C52 "C2012X7R1V475K125AC" 0805_HV 49.2,117.24 r180 top value=4.7uF
C53 "C0603C221J5GAC7867" FP-C0603C221J5GAC7867_0603-IPC_B 54.248,120.523 r270 top value=220pF
C54 "885012206087" 0603 97.028,36.83 r0 top value=4700pF
C55 "885012006057" 0603 50.209,111.818 r90 top value=100pF
C56 "C0603C221J5GAC7867" FP-C0603C221J5GAC7867_0603-IPC_B 49.196,115.302 r0 top value=220pF
C57 "C0603C222K5RAC" 0603 60.2,119.217 r90 top value=2200pF
C58 "C0603C222K5RAC" 0603 58.674,122.809 r0 top value=2200pF
C59 "885012006057" 0603 55.88,120.015 r90 top value=100pF
C60 "C1608X6S1H105K080AC" 0603 62.738,123.444 r270 top value=1uF
C61 "C1608X5R1H473K080AA" 0603 85.988,38.485 r0 top value=0.047uF
C62 "Capacitor" 0603 86.803,35.964 r270 top value=10pF
C63 "885012206087" 0603 90.6,29.666 r90 top value=4700pF
C64 "885012209073" 1210_280 160.274,13.081 r180 top value=10uF
C65 "885012209073" 1210_280 160.258,9.952 r180 top value=10uF
C66 "885012209073" 1210_280 160.274,6.35 r180 top value=10uF
C67 "885012209073" 1210_280 160.274,3.048 r180 top value=10uF
C68 "UCL1V151MCL6GS" SM_RADIAL_10BMM 133.858,37.211 r270 top value=150uF
C69 "GRM188R71E474KA12D" 0603 163.83,26.416 r180 top value=0.47uF
C70 "GRM188R71E474KA12D" 0603 163.874,27.944 r0 top value=0.47uF
C71 "885012209073" 1210_280 159.13,17.747 r270 top value=10uF
C72 "885012209073" 1210_280 155.701,17.747 r270 top value=10uF
C73 "885012209073" 1210_280 152.272,17.747 r270 top value=10uF
C74 "885012209073" 1210_280 148.843,17.747 r270 top value=10uF
C75 "885012209073" 1210_280 163.575,44.162 r0 top value=10uF
C76 "885012209073" 1210_280 163.575,47.338 r0 top value=10uF
C77 "885012209073" 1210_280 147.285,44.745 r270 top value=10uF
C78 "885012209073" 1210_280 144.11,44.745 r270 top value=10uF
C79 "UCL1V151MCL6GS" SM_RADIAL_10BMM 122.174,37.211 r270 top value=150uF
C80 "885012206095" 0603 160.019,30.701 r90 top value=0.1uF
C81 "885012206095" 0603 164.05,35.922 r270 top value=0.1uF
C82 "885012206095" 0603 165.861,39.972 r180 top value=0.1uF
C83 "885012206095" 0603 169.417,39.972 r180 top value=0.1uF
C84 "885012107018" 0805_HV 161.731,35.602 r90 top value=4.7uF
C85 "885012207103" 0805_HV 180.212,26.04 r0 top value=1uF
C86 "885012206095" 0603 180.212,28.034 r180 top value=0.1uF
C87 "885012206076" 0603 162.051,30.701 r270 top value=1uF
C88 "UCL1V151MCL6GS" SM_RADIAL_10BMM 110.109,28.194 r180 top value=150uF
C89 "UCL1V151MCL6GS" SM_RADIAL_10BMM 110.109,39.37 r180 top value=150uF
C90 "UCL1V151MCL6GS" SM_RADIAL_10BMM 113.656,64.258 r180 top value=150uF
C91 "885012206095" 0603 180.944,54.767 r0 top value=0.1uF
C92 "885012208094" FP-885012208094_1206-MFG 174.523,53.518 r270 top
C93 "885012107011" 0805_150 180.619,56.825 r180 top value=22uF
C94 "885012208069" 1206 93.886,106.398 r270 top value=10uF
C95 "885012006053" WCAP-CSGP_0603_L1.6W0.8H0.8_Reflow 94.082,110.487 r90 top value=22pF
C96 "885012206095" 0603 91.743,107.131 r90 top value=0.1uF
C97 "885342208009" 1210 82.303,109.458 r180 top value=0.01uF
C98 "UCL1V151MCL6GS" SM_RADIAL_10BMM 92.115,83.947 r180 top value=150uF
C99 "885012206026" 0603 199.898,44.99 r180 top value=1uF
C100 "885012206095" 0603 199.898,46.609 r0 top value=0.1uF
C101 "885012206083" 0603 195.199,60.452 r180 top value=1000pF
C102 "885012206083" 0603 195.199,58.547 r180 top value=1000pF
C103 "885012206083" 0603 195.199,53.397 r180 top value=1000pF
D1 "DTH8L06DNC" DPAK 58.166,162.687 r90 top
D2 "BAT54HT1G" SOD-323 66.167,150.55 r0 top
D3 "GBU10V08" GBU 22.86,120.658 r0 top value=800V
D4 "S3J-E3/57T" SMC 39.466,175.133 r180 top
D5 "SL1M" SOD-123F 24.765,95.606 r180 top
D6 "SL1M" SOD-123F 24.765,92.329 r180 top
D7 "BAS20HT1G" SOD-323 95.498,69.89 r90 top
D8 "DTH8L06DNC" DPAK 42.746,161.874 r90 top
D9 "BAS20HT1G" SOD-323 93.448,70.183 r270 top
D10 "BAS20HT1G" SOD-323 90.019,63.744 r180 top
D11 "BAT54HT1G" SOD-323 32.544,150.69 r180 top
D12 "BAS20HT1G" SOD-323 83.16,70.79 r270 top
D13 "BAS20HT1G" SOD-323 83.16,66.295 r270 top
D14 "BAS20HT1G" SOD-323 81.957,60.252 r270 top
D15 "BAT54HT1G" SOD-323 41.545,132.084 r0 top
D16 "RB160M-40TR" SOD-123 57.459,98.316 r270 top value=40V
D17 "RB160M-40TR" SOD-123 47.715,102.222 r270 top value=40V
D18 "MM3Z16VST1G" SOD-323 68.58,18.045 r0 top value=16V
D19 "DIODE" SMA 59.474,105.408 r270 top value=US1J-13-F
D20 "SZMM3Z18VST1G" SOD-323 58.608,126.002 r180 top value=18V
D21 "PMEG6010C" SOD-123F 65.073,122.14 r270 top value=PMEG6010CEH,115
D22 "CMDZ15L" SOD-323 164.948,9.005 r0 top value=15V
D23 "BAT46WJ,115" SOD-323F 155.193,32.485 r180 top value=100V
D24 "BAT46WJ,115" SOD-323F 155.193,34.384 r180 top value=100V
D25 "CMDZ15L" SOD-323 123.823,48.129 r0 top value=15V
D26 "150120VS75000" WL_SMCW_GREEN_1206 192.278,30.226 r180 top value=Green
D27 "150120VS75000" WL_SMCW_GREEN_1206 192.305,25.832 r180 top value=Green
D28 "150120VS75000" WL_SMCW_GREEN_1206 192.424,34.668 r180 top value=Green
D29 "MMSZ4689T3G" SOD-123 128.27,54.864 r0 top value=5.1V
D30 "BAS40-04-7-F" SOT-23L 127.761,51.275 r270 top value=40V
D31 "BAT46WJ,115" SOD-323F 136.043,57.404 r270 top value=100V
D32 "BAT46WJ,115" SOD-323F 139.102,56.681 r180 top value=100V
D33 "BAT46WJ,115" SOD-323F 139.102,58.701 r180 top value=100V
D34 "BAT46WJ,115" SOD-323F 88.144,111.639 r0 top value=100V
D35 "ES1J-LTP" SMA 99.968,107.131 r270 top value=600V
D36 "MURA160T3G" SMA 82.805,101.161 r180 top value=600V
D37 "MM3Z16VST1G" SOD-323 100.161,94.148 r270 top value=16V
F1 "SF-3812F500T-2" FP-SF-3812F1500T-2_3812-MFG 13.477,16.51 r0 top value=5A
H1 "V9733E1-LP" FP-V9733E1-LP_THERMAL_HEATSINK_25MM0_42MM0-MFG 22.86,117.61 r180 top
H2 "Bumpon" Bumpon_SJ5003Transparent 210.261,187.122 r180 bottom
H3 "Bumpon" Bumpon_SJ5003Transparent 217.322,12.116 r180 bottom
H4 "Bumpon" Bumpon_SJ5003Transparent 28.499,6.39 r180 bottom
H5 "Bumpon" Bumpon_SJ5003Transparent 135.211,17.229 r180 bottom
H6 "Bumpon" Bumpon_SJ5003Transparent 116.129,190.246 r180 bottom
H7 "Bumpon" Bumpon_SJ5003Transparent 14.909,185.927 r180 bottom
J1 "691213510003" On-Shore_ED120_3DS 13.477,8.89 r0 top
J2 "999-11-113-10-000000" Mill-Max_999-11-113-10-000000 145.098,15.261 r270 top
J3 "691236510003" Wurth_691236510003 131.318,6.096 r0 top
J4 "999-11-113-10-000000" Mill-Max_999-11-113-10-000000 109.263,16.749 r0 top
J5 "61900419521" FP-22-05-3041_HDR4-MFG 177.673,4.742 r0 top
J6 "999-11-113-10-000000" Mill-Max_999-11-113-10-000000 109.263,20.267 r0 top
J7 "691236510003" Wurth_691236510003 110.617,6.223 r0 top
J8 "61300621121" Wurth_61300621121 137.33,62.738 r90 top
J9 "HTSW-110-07-G-D" BOOSTERPACK_40PIN_MALE_PART1 200.152,60.706 r0 top
J10 "HTSW-110-07-G-D" BOOSTERPACK_40PIN_MALE_PART2 156.972,60.706 r0 top
J11 "999-11-113-10-000000" Mill-Max_999-11-113-10-000000 170.053,7.874 r90 top
L1 "750314724" FP-750314724_PTH_XFRMR_23MM5_26MM0-MFG 60.201,186.55 r90 top
L2 "74437529203221" "WE-HCF Round_2920" 13.97,154.94 r0 top value=220uH
L3 "74466340007" Wurth_7446631007 12.7,52.07 r180 top value=0.7mH
L4 "74466340007" Wurth_7446631007 12.688,91.58 r180 top value=0.7mH
L5 "750314724" FP-750314724_PTH_XFRMR_23MM5_26MM0-MFG 15.36,186.55 r90 top
L6 "750371775r00" FP-750371775r00_PTH_22MM0_22MM0-MFG 72.39,87.63 r90 top value=32uH
L7 "7443081030" FP-7443081030_SMT_IND_9MM4_6MM2-MFG 63.246,11.684 r0 top value=300nH
L8 "744325550" WE-HC6 147.273,33.354 r90 top value=5.5uH
L9 "74438335150" WE-MAPI_3015 181.669,51.343 r0 top value=15uH
L10 "7687714471" "WE-PD HV_1060" 92.07,95.735 r180 top value=470uH
LOGO2 "DANGER HIGH VOLTAGE" IEC_HighVoltage_Small 3.7,17.628 r0 top
LOGO3 "DANGER HIGH VOLTAGE" IEC_HighVoltage_Small 26.403,100.734 r0 top
LOGO4 "DANGER HIGH VOLTAGE" IEC_HighVoltage_Small 50.521,171.509 r0 top
LOGO5 "DANGER HIGH VOLTAGE" IEC_HighVoltage_Small 98.662,116.84 r0 top
LOGO6 "CAUTION HOT SURFACE" IEC_HotSurface_Small 76.606,176.174 r0 top
LOGO7 "CAUTION HOT SURFACE" IEC_HotSurface_Small 4.039,137.693 r0 top
NT1 "Net-Tie" Net-Tie_10milWide_30milLong 168.656,37.338 r180 top net-tie
NT2 "Net-Tie" Net-Tie_20milWide_60milLong 49.716,143.747 r315 top net-tie
NT3 "Net-Tie" Net-Tie_20milWide_60milLong 56.795,113.715 r45 top net-tie
Q1 "IPB60R180C7" DDPAK 67.922,160.064 r90 top
Q2 "IPD60R360P7SAUMA1" DPAK 73.147,144.78 r270 top value=IPD60R360P7S
Q3 "IPB60R180C7" DDPAK 33.43,160.17 r90 top
Q4 "MMBT3904LT1G" SOT-23 84.788,60.452 r0 top
Q5 "BSS84LT1G" FP-BSS84LT1G_SOT-23-3-318-08-MFG 84.788,56.448 r90 top
Q6 "MMBT3906-7-F" SOT-23 49.986,131.843 r90 top
Q7 "ISC0603NLSATMA1" FP-ISC0603NLSATMA1_TDSON-8-MFG 34.457,27.579 r0 top value=ISC0603NLS
Q8 "ISC0603NLSATMA1" FP-ISC0603NLSATMA1_TDSON-8-MFG 43.982,27.58 r0 top value=ISC0603NLS
Q9 "IPB60R090CFD7" FP-IPB60R105CFD7ATMA1_D2PAK-MFG 55.499,86.868 r180 top
Q10 "IPB60R090CFD7" FP-IPB60R105CFD7ATMA1_D2PAK-MFG 41.275,93.98 r270 top
Q11 "ISC0603NLSATMA1" FP-ISC0603NLSATMA1_TDSON-8-MFG 69.817,27.58 r0 top value=ISC0603NLS
Q12 "MMBTA05LT1G" SOT-23 62.944,17.545 r270 top
Q13 "ISC0603NLSATMA1" FP-ISC0603NLSATMA1_TDSON-8-MFG 78.907,27.579 r0 top value=ISC0603NLS
Q14 "BSS138LT3G" SOT-23 87.428,29.596 r180 top
Q15 "CSD18534Q5A" DQJ0008A 165.648,4.69 r270 top
Q16 "CSD18534Q5A" DQJ0008A 165.574,13.535 r90 top
Q17 "CSD18534Q5A" DQJ0008A 145.023,52.757 r0 top
Q18 "CSD18534Q5A" DQJ0008A 136.704,52.757 r180 top
Q19 "NTTFS5C670NLTAG" Power_WDFN-8 156.936,42.327 r0 top
Q20 "NTTFS5C670NLTAG" Power_WDFN-8 156.971,24.478 r0 top
Q21 "NTTFS5C670NLTAG" Power_WDFN-8 152.018,24.478 r90 top
Q22 "NTTFS5C670NLTAG" Power_WDFN-8 152.343,42 r270 top
Q23 "SUM110P06-07L-E3" DDPAK 123.063,21.336 r270 top value=SUM110P06
R1 "RC0805JR-072R2L" 0805_HV 62.656,149.452 r90 top value=2.2
R2 "Resistor" 0603 67.922,153.67 r180 top value=10.0k
R3 "ERJ-6GEYJ180V" 0805_HV 66.017,148.26 r0 top value=18
R4 "Resistor" 2512 52.6,155.985 r270 top value=0.03
R5 "Resistor" 2512 48.599,155.985 r270 top value=0.03
R6 "CRCW0603100KFKEA" 0603 77.47,150.831 r270 top value=100k
R7 "RC0603FR-07390KL" 0603 93.536,66.477 r180 top value=390k
R8 "ERJ-8ENF3323V" 1206 26.162,88.392 r90 top value=332k
R9 "ERJ-8ENF3323V" 1206 26.162,83.312 r90 top value=332k
R10 "Resistor" 0603 98.19,73.1 r180 top value=10.0k
R11 "CRCW12061M37FKEA" 1206 70.358,129.286 r0 top value=1.37Meg
R12 "RC0603FR-074K75L" 0603 84.288,63.148 r0 top value=4.75k
R13 "RC0603FR-0722KL" 0603 98.147,71.446 r180 top value=22.0k
R14 "ERJ-8ENF3323V" 1206 26.162,78.124 r90 top value=332k
R15 "RC0805JR-072R2L" 0805_HV 36.944,150.495 r180 top value=2.2
R16 "CRCW12061M37FKEA" 1206 63.373,129.286 r0 top value=1.37Meg
R17 "Resistor" 0603 33.52,153.394 r180 top value=10.0k
R18 "ERJ-6GEYJ180V" 0805_HV 32.854,148.418 r180 top value=18
R19 "RC0603FR-0735K7L" 0603 81.419,72.092 r90 top value=35.7k
R20 "ERJ-3EKF2002V" 0603 97.389,68.961 r270 top value=20.0k
R21 "CRCW12061M37FKEA" 1206 56.261,129.286 r0 top value=1.37Meg
R22 "Resistor" 0603 86.701,73.262 r0 top value=10.0k
R23 "RC0603FR-072M21L" 0603 81.419,68.741 r270 top value=2.21Meg
R24 "RC0603FR-0714K7L" 0603 82.385,74.752 r180 top value=14.7k
R25 "CRCW12063M32FKEA" 1206 35.56,135.73 r180 top value=3.32Meg
R26 "RC0603FR-07124KL" 0603 42.545,137.381 r90 top value=124k
R27 "CRCW12063M32FKEA" 1206 35.56,138.867 r180 top value=3.32Meg
R28 "Resistor" 0603 52.197,149.606 r270 top value=100
R29 "CRCW12063M32FKEA" 1206 35.56,142.091 r180 top value=3.32Meg
R30 "ERJ-6ENF1072V" 0805_HV 41.619,148.401 r180 top value=10.7k
R31 "ERJ-6ENF1072V" 0805_HV 40.419,141.248 r180 top value=10.7k
R32 "Resistor" 0603 89.13,56.223 r90 top value=10.0k
R33 "RC0603FR-07158KL" 0603 56.769,137.795 r90 top value=158k
R34 "RC0603FR-0715KL" 0603 52.019,135.484 r180 top value=15.0k
R35 "RC0603FR-0747K5L" 0603 79.723,55.446 r0 top value=47.5k
R36 "RC0603FR-07200KL" 0603 49.099,137.414 r270 top value=200k
R37 "RC0603FR-07182KL" 0603 56.134,147.828 r0 top value=182k
R38 "CRCW0603100KFKEA" 0603 41.218,133.858 r0 top value=100k
R39 "RC0603FR-074K75L" 0603 80.335,40.513 r0 top value=4.75k
R40 "RC0603FR-07287KL" 0603 44.196,137.414 r90 top value=287k
R41 "RC0603FR-0726K7L" 0603 56.134,146.431 r180 top value=26.7k
R42 "RC0603FR-0780K6L" 0603 45.847,137.414 r90 top value=80.6k
R43 "CRCW12061M37FKEA" 1206 63.465,141.205 r180 top value=1.37Meg
R44 "CRCW12061M37FKEA" 1206 66.311,136.436 r90 top value=1.37Meg
R45 "CRCW12061M37FKEA" 1206 70.358,132.207 r180 top value=1.37Meg
R46 "RC0603FR-0780K6L" 0603 59.944,137.795 r90 top value=80.6k
R47 "RC0603FR-0747K5L" 0603 82.243,56.304 r270 top value=47.5k
R48 "RC0805JR-072R2L" 0805_HV 38.481,23.724 r90 top value=2.2
R49 "RC0805JR-072R2L" 0805_HV 47.965,23.724 r90 top value=2.2
R50 "RC0805JR-072R2L" 0805_HV 55.118,98.171 r270 top value=2.2
R51 "Resistor" 0805_HV1 53.086,98.171 r270 top value=10
R52 "RC1206FR-0722RL" 1206 50.419,24.13 r270 top value=22.0
R53 "Resistor" 0603 55.499,92.643 r0 top value=10.0k
R54 "RC0805JR-072R2L" 0805_HV 39.37,101.459 r180 top value=2.2
R55 "RC0805JR-072R2L" 0805_HV 73.914,23.801 r90 top value=2.2
R56 "Resistor" 0805_HV1 39.37,103.603 r180 top value=10
R57 "Resistor" 0603 36.466,94.029 r90 top value=10.0k
R58 "CRCW0805150RFKEA" 0805_HV 48.211,112.09 r270 top value=150
R59 "RC0805JR-072R2L" 0805_HV 82.931,23.749 r90 top value=2.2
R60 "RC0603FR-076K81L" 0603 65.535,17.304 r270 top value=6.81k
R61 "RMCF0603ZT0R00" 0603 57.435,18.44 r0 top value=0
R62 "RC1206FR-0722RL" 1206 65.28,25.681 r270 top value=22.0
R63 "RC0805JR-072R2L" 0805_HV 55.499,103.408 r180 top value=2.2
R64 "RC0603FR-07649KL" 0603 50.175,120.015 r90 top value=649k
R65 "RC0603FR-0749R9L" 0603 94.517,34.214 r270 top value=49.9
R66 "CRCW12063M32FKEA" 1206 73.279,125.349 r90 top value=3.32Meg
R67 "RC0603FR-07162KL" 0603 52.705,120.65 r270 top value=162k
R68 "CRCW12063M32FKEA" 1206 69.193,124.149 r0 top value=3.32Meg
R69 "CRCW0603100KFKEA" 0603 48.514,120.015 r90 top value=100k
R70 "Resistor" 0603 94.493,37.685 r270 top value=6.04k
R71 "CRCW12063M32FKEA" 1206 64.045,126.352 r0 top value=3.32Meg
R72 "RC0603FR-071KL" 0603 97.027,38.549 r0 top value=1.00k
R73 "Resistor" 0805_HV1 66.421,118.11 r0 top value=10
R74 "RC0603FR-07130KL" 0603 92.473,35.964 r270 top value=130k
R75 "RC0603FR-0726K1L" 0603 46.989,120.015 r90 top value=26.1k
R76 "RC0603FR-0736K5L" 0603 58.62,119.217 r270 top value=36.5k
R77 "B57371V2474J060" FP-B57371V2474J060_0603-MFG 58.674,121.412 r180 top value=470k
R78 "Resistor" 0603 94.466,41.478 r180 top value=6.04k
R79 "RC0603FR-0712K4L" 0603 58.674,124.333 r180 top value=12.4k
R80 "CRCW0603100KFKEA" 0603 61.214,123.444 r270 top value=100k
R81 "Resistor" 0603 85.217,35.941 r270 top value=10.0k
R82 "RMCF0603ZT0R00" 0603 62.886,118.11 r0 top value=0
R83 "RC0603FR-0795K3L" 0603 86.694,32.919 r270 top value=95.3k
R84 "RC0603FR-071KL" 0603 91.44,27.051 r180 top value=1.00k
R85 "RC0603FR-0715KL" 0603 88.336,32.924 r90 top value=15.0k
R86 "CRCW0603100KFKEA" 0603 92.291,29.648 r90 top value=100k
R87 "580070763001" 2512 165.861,19.525 r180 top value=0.002
R88 "560050316012" FP-560050316012_0603-IPC_B 167.64,22.225 r0 top value=10
R89 "560050316012" FP-560050316012_0603-IPC_B 164.083,22.225 r180 top value=10
R90 "CRCW0603475KFKEA" 0603 166.497,25.146 r270 top value=475k
R91 "RMCF0603ZT0R00" 0603 155.32,28.796 r0 top value=0
R92 "RMCF0603ZT0R00" 0603 155.32,37.94 r0 top value=0
R93 "560050316012" FP-560050316012_0603-IPC_B 136.154,48.705 r180 top value=10
R94 "RMCF0603ZT0R00" 0603 155.32,30.574 r0 top value=0
R95 "RMCF0603ZT0R00" 0603 155.32,36.162 r0 top value=0
R96 "580070763005" 2512 134.454,45.974 r0 top value=0.005
R97 "560050316012" FP-560050316012_0603-IPC_B 132.604,48.705 r0 top value=10
R98 "RMCF0603ZT0R00" 0603 164.083,30.701 r90 top value=0
R99 "RC0603FR-07113KL" 0603 168.275,25.146 r90 top value=113k
R100 "RT0603DRE072K58L" 0603 170.18,25.146 r270 top value=2.58k
R101 "RC0603FR-07249KL" 0603 172.212,42.799 r270 top value=249k
R102 "RC0603FR-0715KL" 0603 172.973,39.972 r0 top value=15.0k
R103 "RT0603DRE074K22L" 0603 171.958,25.146 r90 top value=4.22k
R104 "RC0603FR-071KL" 0603 192.686,32.309 r180 top value=1.00k
R105 "RC0603FR-071KL" 0603 192.659,27.813 r180 top value=1.00k
R106 "RC0603FR-071KL" 0603 192.659,36.703 r180 top value=1.00k
R107 "RC0603FR-0766K5L" 0603 180.212,29.685 r180 top value=66.5k
R108 "CRCW060324K3FKEA" 0603 180.212,36.289 r180 top value=24.3k
R109 "RC0603FR-074K99L" 0603 180.212,37.94 r180 top value=4.99k
R110 "CRCW20101K00FKEF" 2010 120.268,53.307 r180 top value=1.00k
R111 "RT0603BRD0730K1L" 0603 180.212,32.987 r180 top value=30.1k
R112 "RT0603BRD075K23L" 0603 180.212,34.638 r180 top value=5.23k
R113 "CRCW0603100KDHEAP" 0603 127.761,48.129 r180 top value=100k
R114 "RC0603FR-0751KL" 0603 176.554,58.67 r0 top value=51.0k
R115 "RC0603FR-0722KL" 0603 176.579,57.088 r180 top value=22.0k
R116 "ERJ-8ENF2373V" 1206 96.749,110.12 r270 top value=237k
R117 "ERJ-8ENF2373V" 1206 96.749,105.431 r270 top value=237k
R118 "RC0603FR-0718K7L" 0603S 91.395,109.854 r180 top value=18.7k
R119 "RMCF0603ZT0R00" 0603 91.748,103.652 r90 top value=0
R120 "CRCW080547R5FKEA" 0805_HV 99.968,98.63 r90 top value=47.5
R121 "RC0603FR-074K75L" 0603 195.199,68.961 r180 top value=4.75k
R122 "RC0603FR-074K75L" 0603 195.199,70.739 r180 top value=4.75k
R123 "RC0603FR-074K75L" 0603 195.199,67.183 r180 top value=4.75k
R124 "RC0603FR-074K75L" 0603 180.212,31.336 r180 top value=4.75k
R125 "RC0603FR-0710KL" 0603 195.199,62.103 r180 top value=10.0k
R126 "CRCW0603110KFKEA" 0603 195.199,63.754 r0 top value=110k
R127 "RC0603FR-0710KL" 0603 195.199,56.896 r180 top value=10.0k
R128 "RC0603FR-0710KL" 0603 195.199,51.689 r180 top value=10.0k
R129 "CRCW0603110KFKEA" 0603 195.199,50.033 r180 top value=110k
R130 "CRCW0603110KFKEA" 0603 195.199,55.171 r180 top value=110k
R131 "RC0603FR-074K75L" 0603 161.006,51.458 r90 top value=4.75k
R132 "RC0603FR-0751KL" 0603 91.743,111.639 r180 top value=51.0k
RT1 "B57237S0220M000" S237 87.055,144.78 r180 top value=22
RV1 "V275SM7" VAR_SM7-Series_H 13.477,24.13 r0 top value=275VAC
T1 "750371772r00" FP-750371772r00_PTH16_41MM9_44MM0-MFG 53.467,53.467 r270 top
TP1 "5000" Keystone5000 97.79,199.39 r90 top
TP2 "5000" Keystone5000 22.86,171.825 r90 top
TP3 "5004" Keystone5004 66.04,171.45 r90 top
TP4 "5001" Keystone5001 73.037,171.45 r90 top
TP5 "5002" Keystone5002 22.427,23.667 r90 top
TP6 "5004" Keystone5004 62.595,145.168 r90 top
TP7 "5001" Keystone5001 67.556,145.154 r90 top
TP8 "5002" Keystone5002 4.447,23.667 r90 top
TP9 "5001" Keystone5001 60.063,153.195 r90 top
TP10 "5004" Keystone5004 74.472,154.395 r90 top
TP11 "5004" Keystone5004 94.312,63.928 r90 top
TP12 "5004" Keystone5004 32.385,172.339 r90 top
TP13 "5004" Keystone5004 31.838,145.57 r90 top
TP14 "5004" Keystone5004 99.662,64.781 r90 top
TP15 "5001" Keystone5001 39.416,153.92 r90 top
TP16 "5004" Keystone5004 78.88,65.728 r90 top
TP17 "5000" Keystone5000 56.515,150.876 r90 top
TP18 "5004" Keystone5004 12.7,171.831 r90 top
TP19 "5004" Keystone5004 36.165,145.57 r90 top
TP20 "5004" Keystone5004 57.584,171.45 r90 top
TP21 "5004" Keystone5004 89.299,60.152 r90 top
TP22 "5004" Keystone5004 49.463,128.27 r90 top
TP23 "5000" Keystone5000 97.536,30.226 r90 top
TP24 "5001" Keystone5001 97.663,25.4 r90 top
TP25 "5004" Keystone5004 97.536,34.163 r90 top
TP26 "5000" Keystone5000 99.78,87.79 r90 top
TP27 "5001" Keystone5001 99.78,79.697 r90 top
U1 "TLV1812DR" D0008A-MFG 88.646,69.694 r180 top
U2 "LM4040D50QDBZR" DBZ0003A_N 94.724,74.138 r270 top
U3 "UCC28065DR" D0016A_N 49.075,143.736 r90 top
U4 "SFH6156-2T" SMD-4 87.86,48.425 r270 top
U5 "SFH6156-2T" SMD-4 80.875,48.425 r90 top
U6 "UCC24624DR" D0008A_N 57.617,22.25 r0 top
U7 "UCC256603DDBR" DDB0014A-MFG 56.626,113.87 r270 top
U8 "SFH6156-2T" SMD-4 94.592,48.425 r90 top
U9 "ATL431LIAQDBZR" DBZ0003A_N 89.553,35.964 r0 top
U10 "BQ25751RRVT" RRV0036A-MFG 170.941,33.495 r180 top
U11 "TPS560430XDBVR" DBV0006A_N 177.504,53.685 r270 top
U12 "UCC28910DR" D0007A_N 87.644,106.787 r90 top

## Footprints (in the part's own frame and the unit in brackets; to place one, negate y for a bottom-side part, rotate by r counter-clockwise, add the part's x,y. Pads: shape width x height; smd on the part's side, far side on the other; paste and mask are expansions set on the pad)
0603 [mm] "0603 from SM-752 data"
  rect 1x0.95 smd: 1(-0.8,0) 2(0.8,0)
  silkscreen extent -1.52,-0.69 1.52,0.69, body extent -0.87,-0.47 0.87,0.47, height 1
0603S [mil]
  rect 20x35 smd: 1(-30,0) 2(30,0)
  body extent -34,-19 34,19, height 39
0805_150 [mm] "0805 / 1.5 mm height"
  rect 1.15x1.45 smd: 1(-0.9,0) 2(0.9,0)
  silkscreen extent -0.1,-0.8 0.1,0.8, body extent -1.1,-0.72 1.1,0.72, height 1.5
0805_HV [mil] "0805 with 30mil clearance between pads"
  rect 50x63 smd: 1(-40,0) 2(40,0)
  silkscreen extent -74,-40 74,40, body extent -43,-29 43,29, height 57
0805_HV1 [mm] "Custom footprint based on analyzing multiple manufacturer recommendations"
  rrect10% 1x1.25 smd: 1(-1,0) 2(1,0)
  silkscreen extent -0.2,-0.75 0.2,0.75, body extent -1.1,-0.72 1.1,0.73, height 1.45
1206 [mm] "1206 from SM-752 data"
  rect 1.3x1.85 smd: 1(-1.45,0) 2(1.45,0)
  silkscreen extent -2.4,-1.21 2.4,1.21, body extent -1.7,-0.9 1.7,0.9, height 1.35
1210 [mm] "1210 from SM-752 data"
  rect 1.3x2.7 smd: 1(-1.45,0) 2(1.45,0)
  silkscreen extent -2.32,-1.57 2.32,1.57, body extent -1.7,-1.35 1.7,1.35, height 1.35
1210_280 [mm] "SMD, 2-Leads, Body 3.6x2.8mm, Height 2.8mm"
  rect 1.1x2.2 smd: 1(-1.65,0) 2(1.65,0)
  silkscreen extent -0.84,-1.4 0.84,1.4, body extent -1.8,-1.4 1.8,1.4, height 2.8
1812_254 [mm] "SMD, 2-Leads, Body 4.8x3.4mm"
  rect 1.6x3.4 smd: 1(-2,0) 2(2,0)
  silkscreen extent -0.8,-1.7 0.8,1.7, body extent -2.4,-1.7 2.4,1.7, height 2.54
2010 [mm] "Chip Capacitor, Body 5.08x2.54mm, IPC Medium Density"
  rect 1.6x2.7 smd: 1(-2.3,0) 2(2.3,0)
  silkscreen extent -3.42,-1.65 3.42,1.65, body extent -2.73,-1.45 2.73,1.45, height 1.66
2512 [mm] "Chip Resistor, Body 6.3x3.2mm, IPC Medium Density"
  rect 1.3x3.4 smd: 1(-2.95,0) 2(2.95,0)
  silkscreen extent -1.9,-1.6 1.9,1.6, body extent -3.22,-1.67 3.22,1.67, height 0.71
BOOSTERPACK_40PIN_MALE_PART1 [mm]
  rect 1.57x1.57 hole 1.02 paste-2539.97 mask+0: 1(1.27,-11.43)
  round 1.57 hole 1.02 paste-2539.97 mask+0: 2(1.27,-8.89) 3(1.27,-6.35) 4(1.27,-3.81) 5(1.27,-1.27) 6(1.27,1.27) 7(1.27,3.81) 8(1.27,6.35) 9(1.27,8.89) 10(1.27,11.43) 21(-1.27,-11.43) 22(-1.27,-8.89) 23(-1.27,-6.35) 24(-1.27,-3.81) 25(-1.27,-1.27) 26(-1.27,1.27) 27(-1.27,3.81) 28(-1.27,6.35) 29(-1.27,8.89) 30(-1.27,11.43)
  silkscreen extent -2.58,-12.76 2.58,12.76, body extent -2.68,-12.86 2.68,12.86, height 0.25
BOOSTERPACK_40PIN_MALE_PART2 [mm]
  rect 1.57x1.57 hole 1.02 paste-2539.97 mask+0: 11(-1.27,11.43)
  round 1.57 hole 1.02 paste-2539.97 mask+0: 12(-1.27,8.89) 13(-1.27,6.35) 14(-1.27,3.81) 15(-1.27,1.27) 16(-1.27,-1.27) 17(-1.27,-3.81) 18(-1.27,-6.35) 19(-1.27,-8.89) 20(-1.27,-11.43) 31(1.27,11.43) 32(1.27,8.89) 33(1.27,6.35) 34(1.27,3.81) 35(1.27,1.27) 36(1.27,-1.27) 37(1.27,-3.81) 38(1.27,-6.35) 39(1.27,-8.89) 40(1.27,-11.43)
  silkscreen extent -2.58,-12.76 2.58,12.76, body extent -2.68,-12.86 2.68,12.86, height 0.25
Bumpon_SJ5003Transparent [mil] "3M Hemispherical Bumpon transparent"
  round 1 on Mech4: 0(0,0)
  silkscreen extent -228,-228 228,228, body extent -218,-218 219,218, height 197
D0007A_N [mm] "SOIC, 7-Leads, Body 4.9x3.9mm, Pitch 1.27mm, IPC Medium Density"
  oval 1.45x0.6 smd: 1(-2.725,1.905) 2(-2.725,0.635) 3(-2.725,-0.635) 4(-2.725,-1.905) 5(2.725,-1.905) 6(2.725,-0.635) 8(2.725,1.905)
  silkscreen extent -3.32,-2.5 1.1,2.52, body extent -3.01,-2.45 3.01,2.45, height 1.75
D0008A-MFG [mm]
  rrect17% 1.55x0.6 smd paste+0 mask+0: 1(-2.7,1.905) 2(-2.7,0.635) 3(-2.7,-0.635) 4(-2.7,-1.905) 5(2.7,-1.905) 6(2.7,-0.635) 7(2.7,0.635) 8(2.7,1.905)
  silkscreen extent -4.18,-2.5 1.5,2.5, body extent -3.57,-2.75 3.57,2.75, height 0.25
D0008A_N [mm] "SOIC, 8-Leads, Body 4.9x3.9mm, Pitch 1.27mm, IPC Medium Density"
  oval 1.45x0.6 smd: 1(-2.725,1.905) 2(-2.725,0.635) 3(-2.725,-0.635) 4(-2.725,-1.905) 5(2.725,-1.905) 6(2.725,-0.635) 7(2.725,0.635) 8(2.725,1.905)
  silkscreen extent -3.3,-2.5 0.9,2.5, body extent -3,-2.45 3,2.45, height 1.63
D0016A_N [mm] "SOIC, 16-Leads, Body 9.9x3.9mm, Pitch 1.27mm, IPC Medium Density"
  oval 1.45x0.6 smd: 1(-2.725,4.445) 2(-2.725,3.175) 3(-2.725,1.905) 4(-2.725,0.635) 5(-2.725,-0.635) 6(-2.725,-1.905) 7(-2.725,-3.175) 8(-2.725,-4.445) 9(2.725,-4.445) 10(2.725,-3.175) 11(2.725,-1.905) 12(2.725,-0.635) 13(2.725,0.635) 14(2.725,1.905) 15(2.725,3.175) 16(2.725,4.445)
  silkscreen extent -3.3,-5 0.9,5, body extent -3,-4.95 3,4.95, height 1.6
DBV0006A_N [mm] "SOT23, 6-Leads, Body 2.9x1.6mm, Pitch 0.95mm, Lead Span 2.8mm, IPC Medium Density"
  rrect17% 1x0.6 smd: 1(-1.375,0.95) 2(-1.375,0) 3(-1.375,-0.95) 4(1.375,-0.95) 5(1.375,0) 6(1.375,0.95)
  silkscreen extent -1.68,-1.55 0.5,1.55, body extent -1.42,-1.46 1.42,1.46, height 1.12
DBZ0003A_N [mm] "SOT23, 3-Leads, Body 2.9x1.3mm, Pitch 0.95mm, Lead Span 2.4mm, IPC Medium Density"
  rrect17% 1x0.6 smd: 1(-1.2,0.95) 2(-1.2,-0.95) 3(1.2,0)
  silkscreen extent 0.2,-1.5 0.7,1.5, body extent -1.26,-1.46 1.26,1.46, height 0.98
DDB0014A-MFG [mm]
  rrect17% 1.55x0.6 smd paste+0 mask+0: 1(-2.7,4.445) 3(-2.7,1.905) 4(-2.7,0.635) 5(-2.7,-0.635) 6(-2.7,-1.905) 7(-2.7,-3.175) 8(-2.7,-4.445) 9(2.7,-4.445) 10(2.7,-3.175) 11(2.7,-1.905) 12(2.7,-0.635) 14(2.7,1.905) 15(2.7,3.175) 16(2.7,4.445)
  silkscreen extent -2.96,-5 2,5.7, body extent -3.57,-5.25 3.57,5.25, height 0.25
DDPAK [mil] "D2-PAK, 3-Pads, Body 9.7x10.4mm (max), TO-263AB, using Vishay Silionix recommended pad sizes"
  rrect8% 135x49.49 smd: 1(-246.06,100) 3(-246.06,-100)
  rrect1% 355x420 smd paste-181.1: 2(155.51,0)
  body extent -295,-202 324,202, height 180
DPAK [mm] "D-PAK, 3-Pads, Body 6.22x6.73mm (max), TO-252AA using nominal STEP model"
  rrect6% 2.6x1.6 smd: 1(-3.4,2.28) 3(-3.4,-2.28)
  rrect2% 6.2x5.8 smd paste-3: 2(3.4,0)
  body extent -3.86,-3.29 5.84,3.29, height 2.48
DQJ0008A [mm] "SMD, 8-Leads, Body 5.75x4.9mm"
  rrect39% 0.91x0.51 smd paste-0.05 mask-0.05: 1(-2.795,1.905) 2(-2.795,0.635) 3(-2.795,-0.635) 4(-2.795,-1.905) 5(2.795,-1.905) 6(2.795,-0.635) 7(2.795,0.635) 8(2.795,1.905)
  rrect8% 1.58x1.25 on Top Paste: 9(-0.38,1.45) 9(-0.38,0) 9(-0.38,-1.45) 9(1.4,1.45) 9(1.4,0) 9(1.4,-1.45)
  rrect3% 3.48x4.47 on Top Solder: 9(0.55,0)
  rrect2% 4.49x4.57 smd paste-2.5 mask-2.5: 9(1.005,0)
  silkscreen extent -3,-2.6 3,2.6, body extent -3.13,-2.45 3.13,2.45, height 1.15
FP-22-05-3041_HDR4-MFG [mm]
  rrect6% 1.57x1.57 hole 1.02 paste-2539.97 mask+0: 1(-3.81,7.073)
  round 1.57 hole 1.02 paste-2539.97 mask+0: 2(-1.27,7.073) 3(1.27,7.073) 4(3.81,7.073)
  silkscreen extent -6.13,1.03 5.08,6.44, body extent -5.18,-6.28 5.18,7.96, height 0.25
